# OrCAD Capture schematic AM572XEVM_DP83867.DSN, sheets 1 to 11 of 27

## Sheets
1 P01_TITLE PAGE: rev: A4; note: am572x_gp_evm_REV_A4.dsn
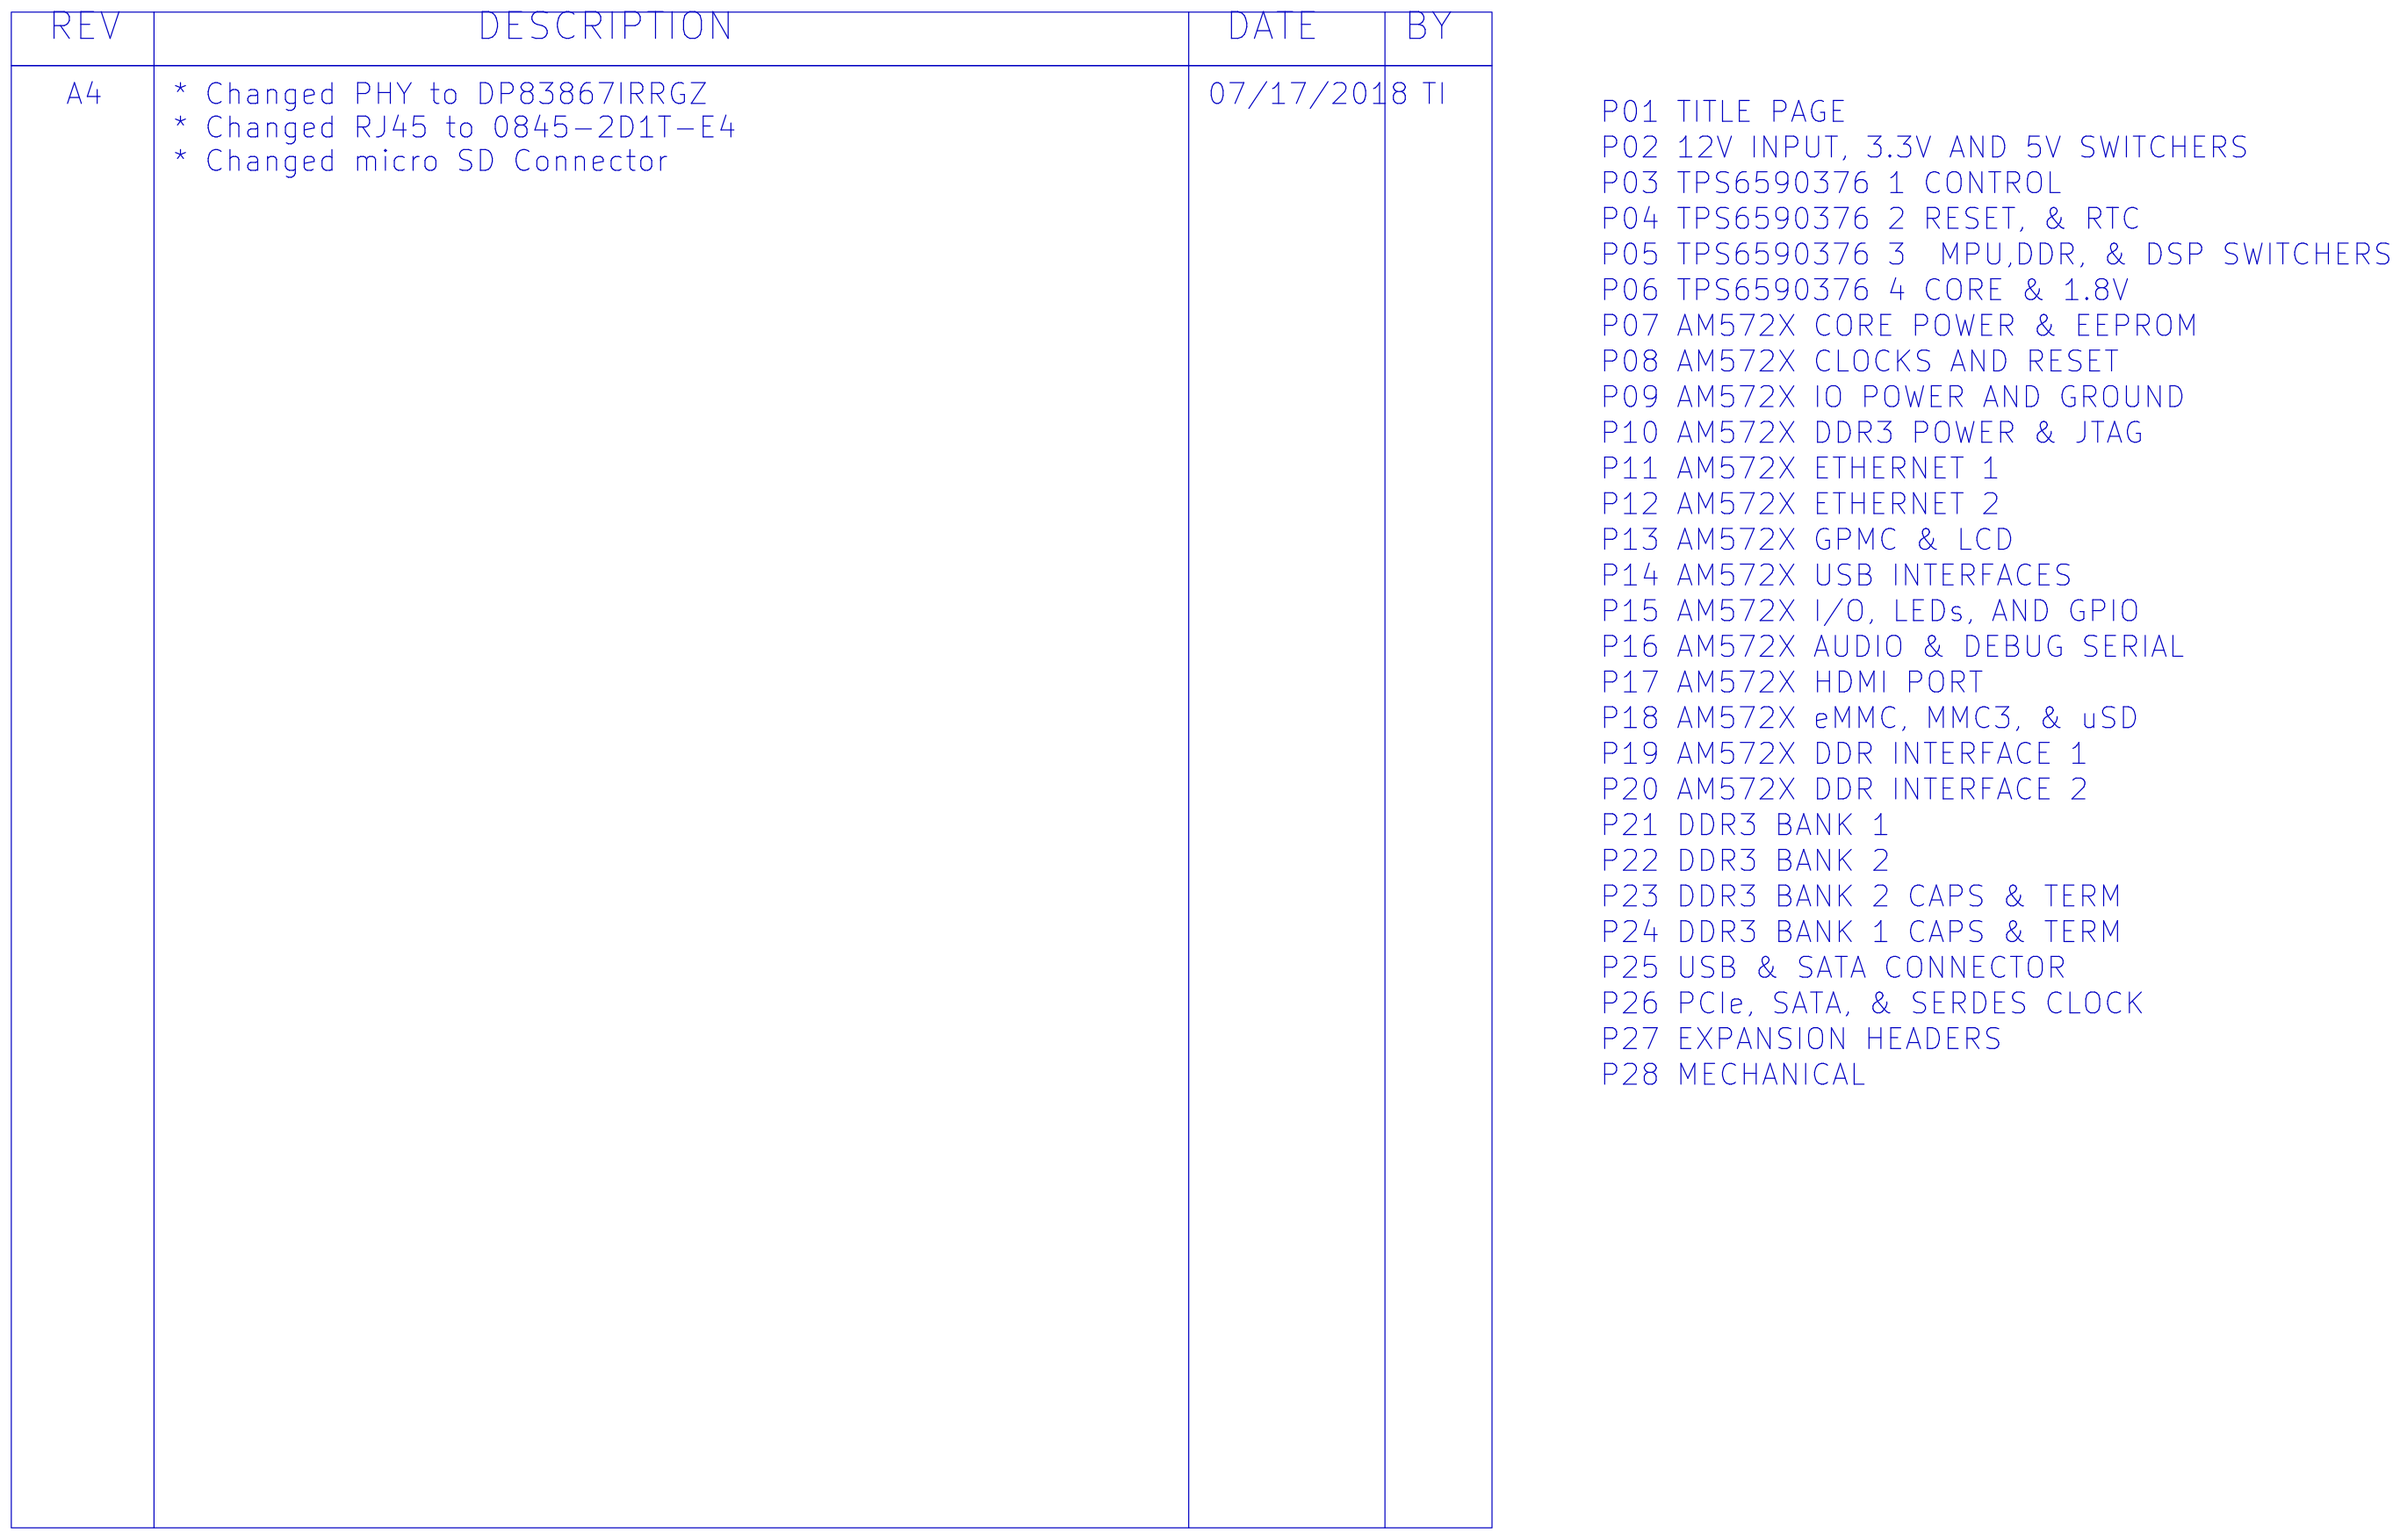
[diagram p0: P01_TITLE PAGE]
2 P02_12V IN, 3.3V & 5V SWITCHERS: size B
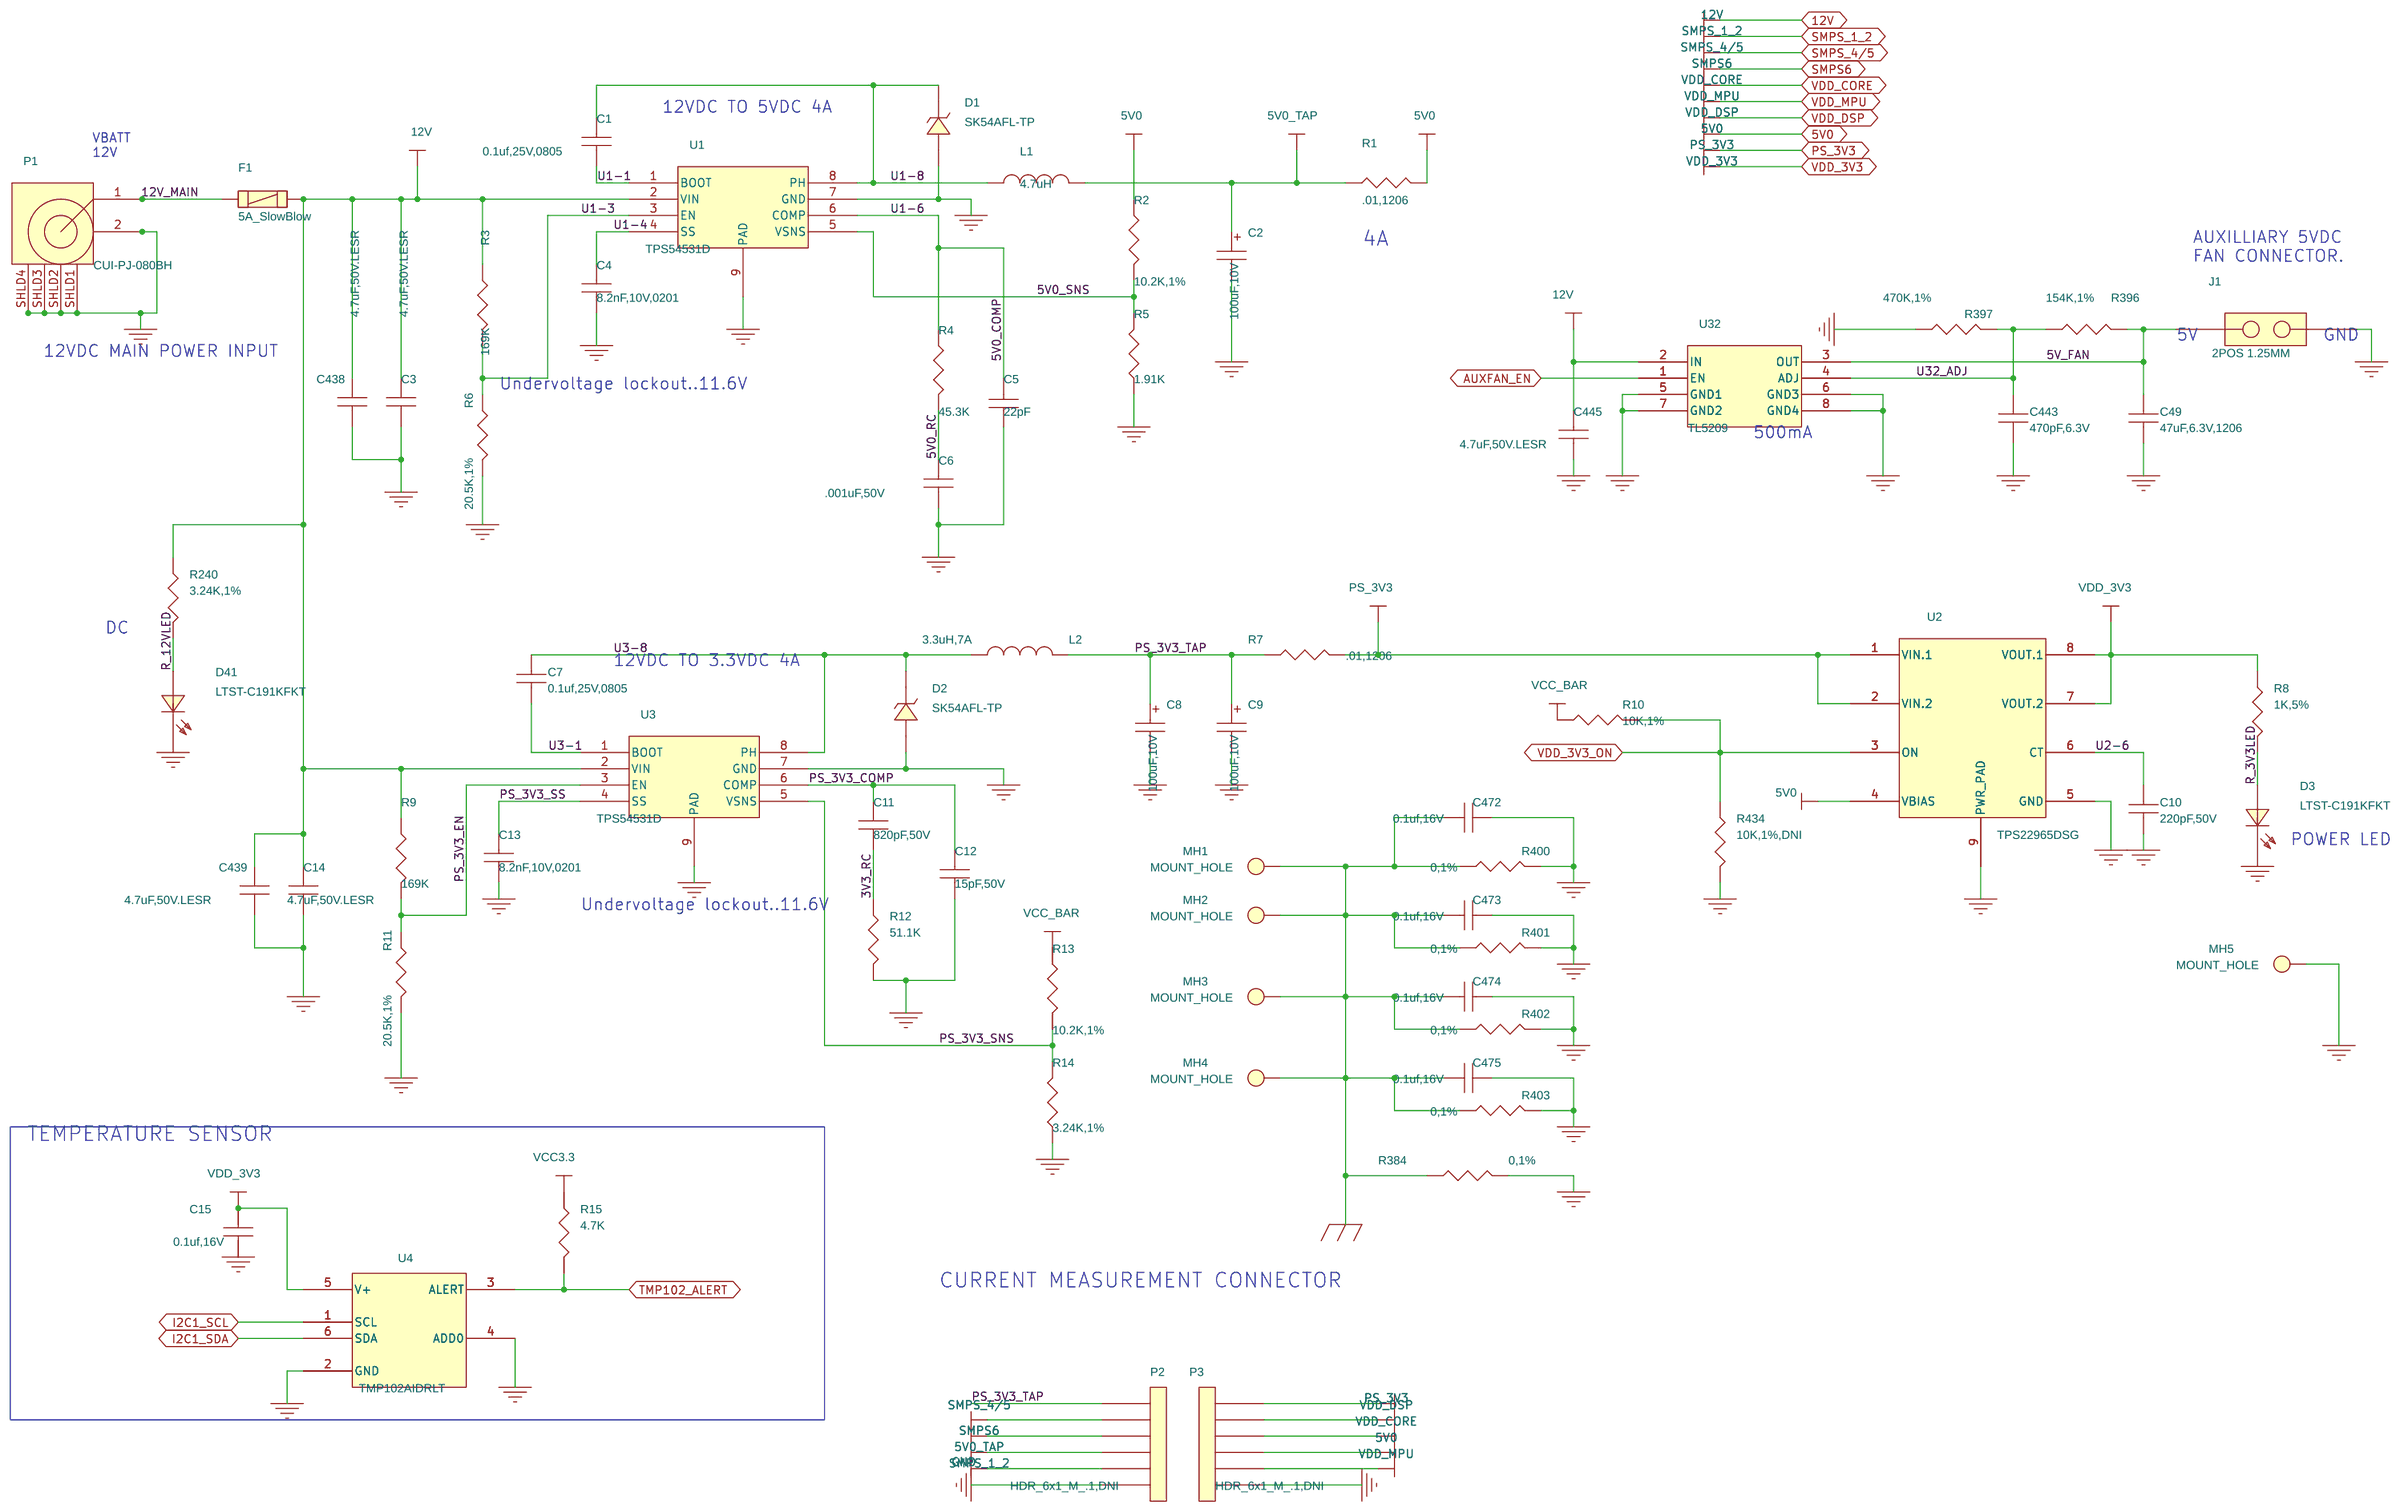
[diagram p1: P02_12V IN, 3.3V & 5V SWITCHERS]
3 P03_TPS6590376 CONTROL: size B
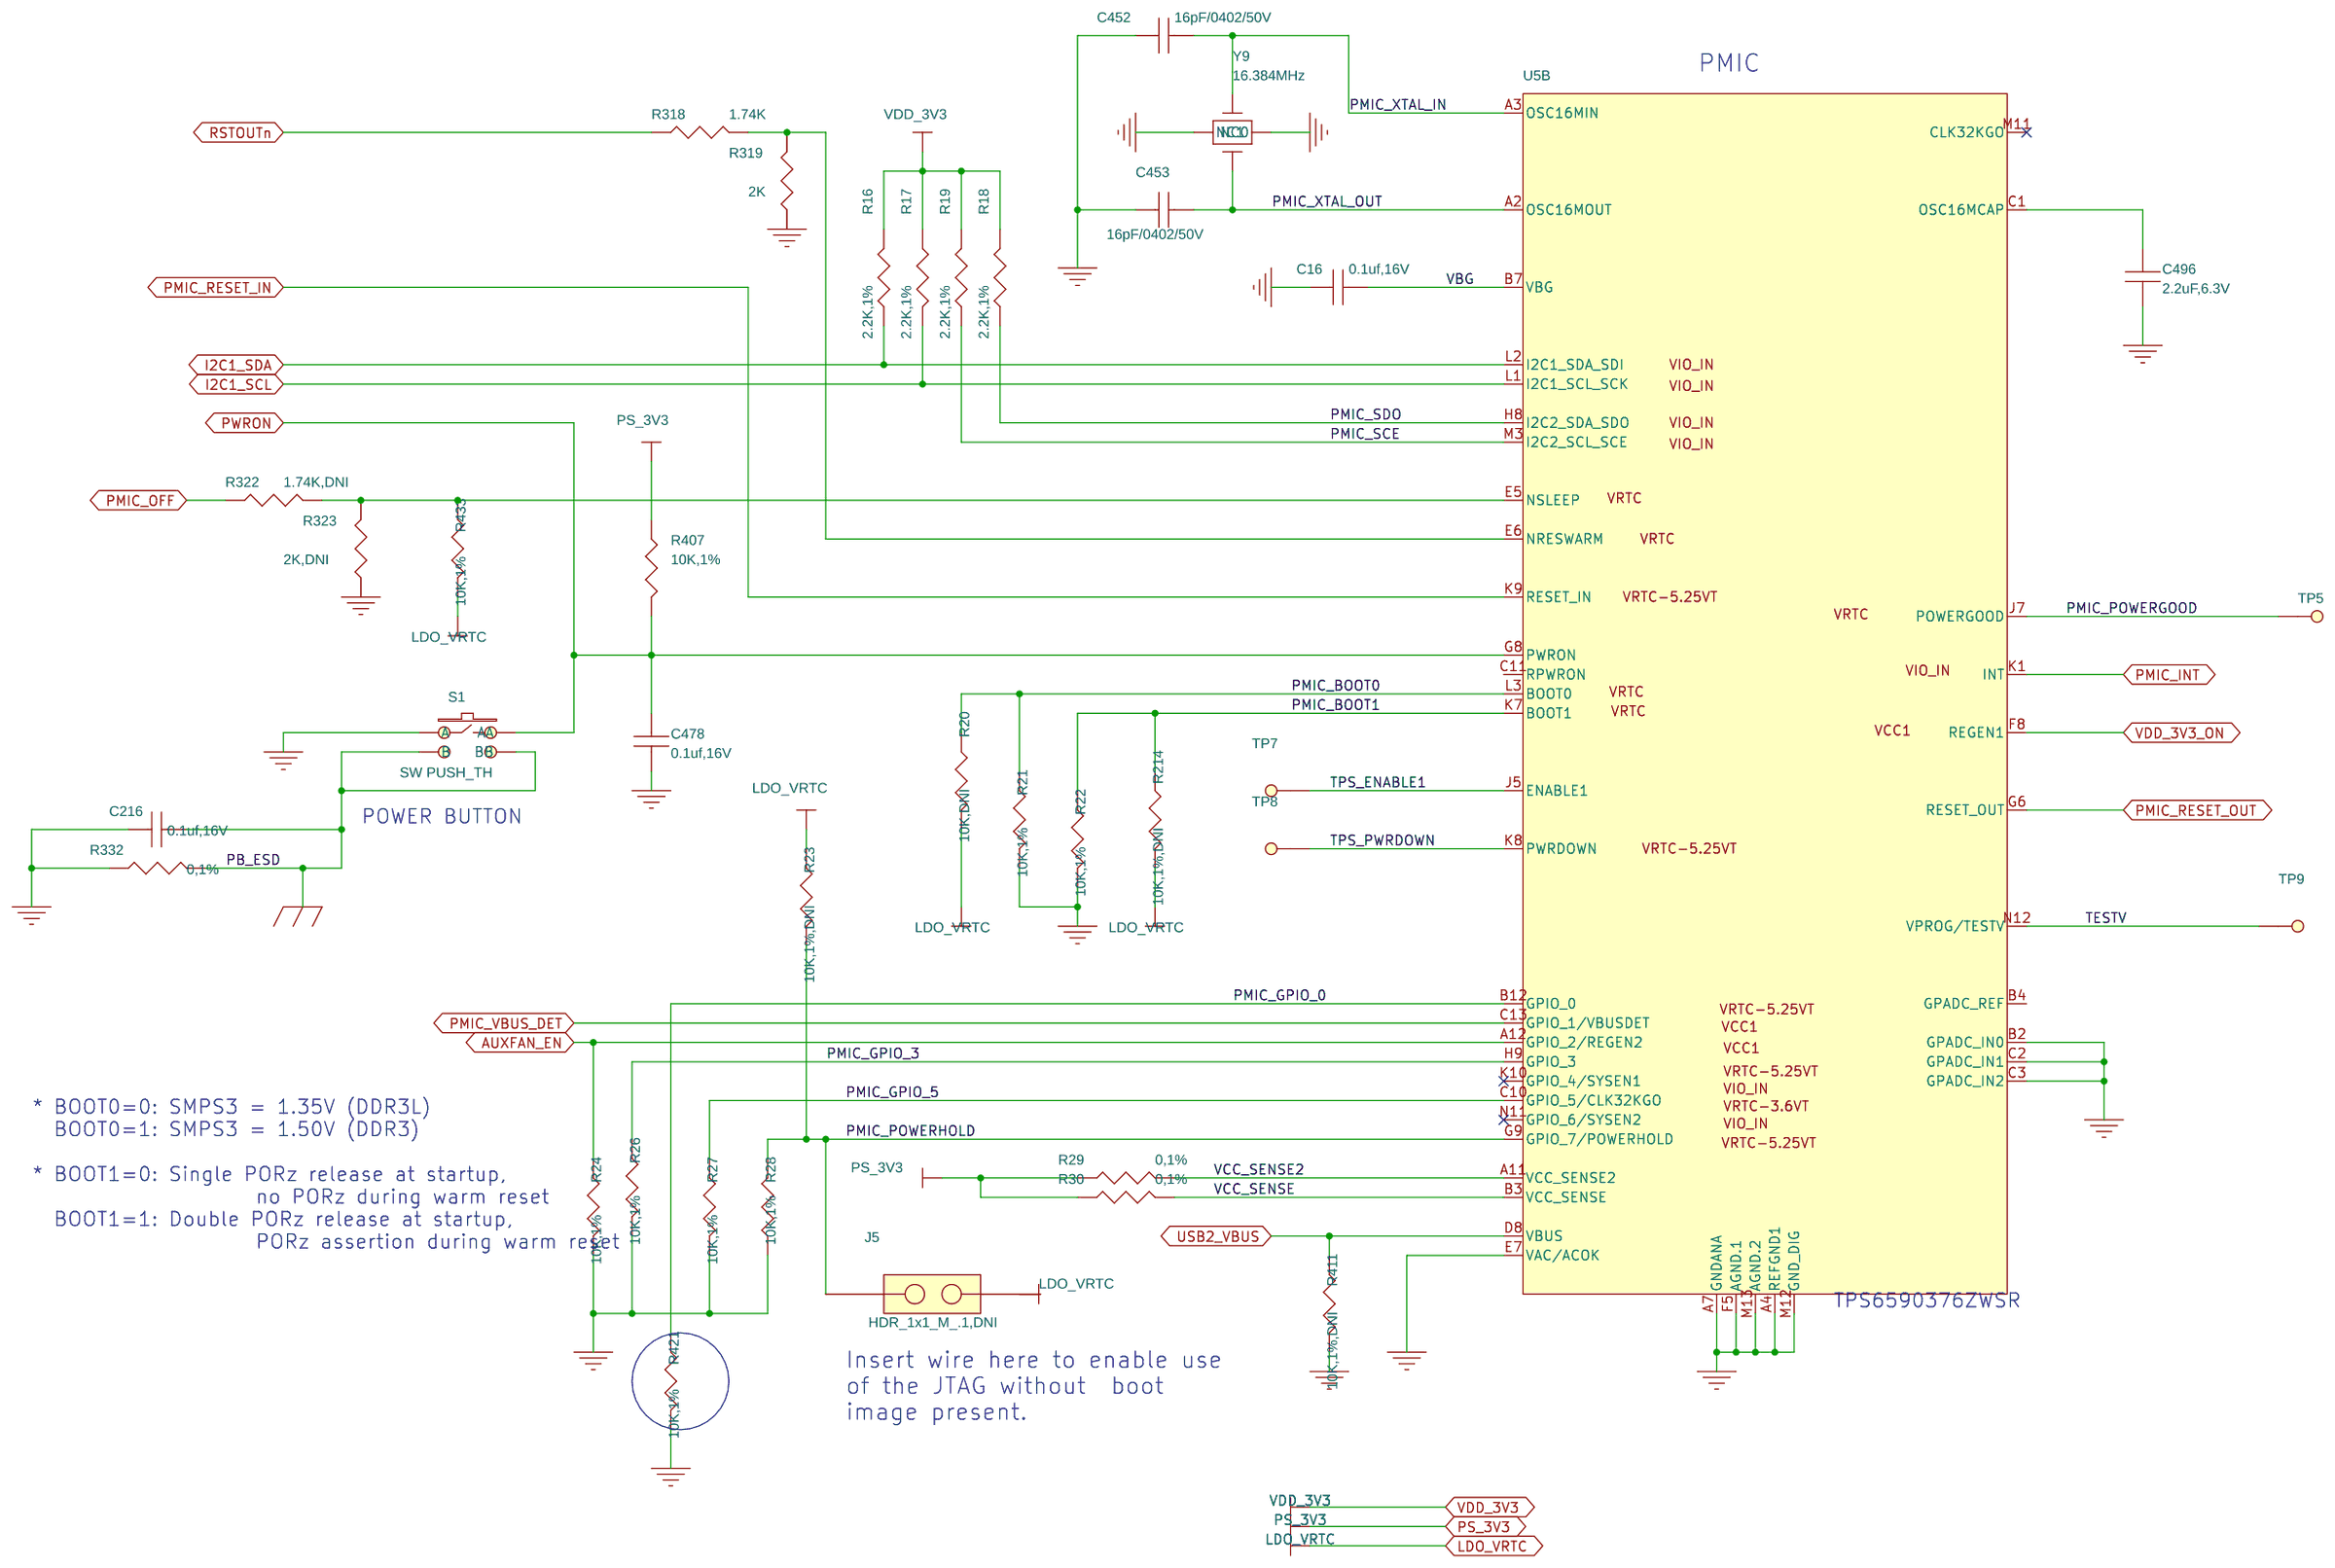
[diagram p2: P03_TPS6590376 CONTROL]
4 P04_TPS6590376 2, LDO & RTC: size B
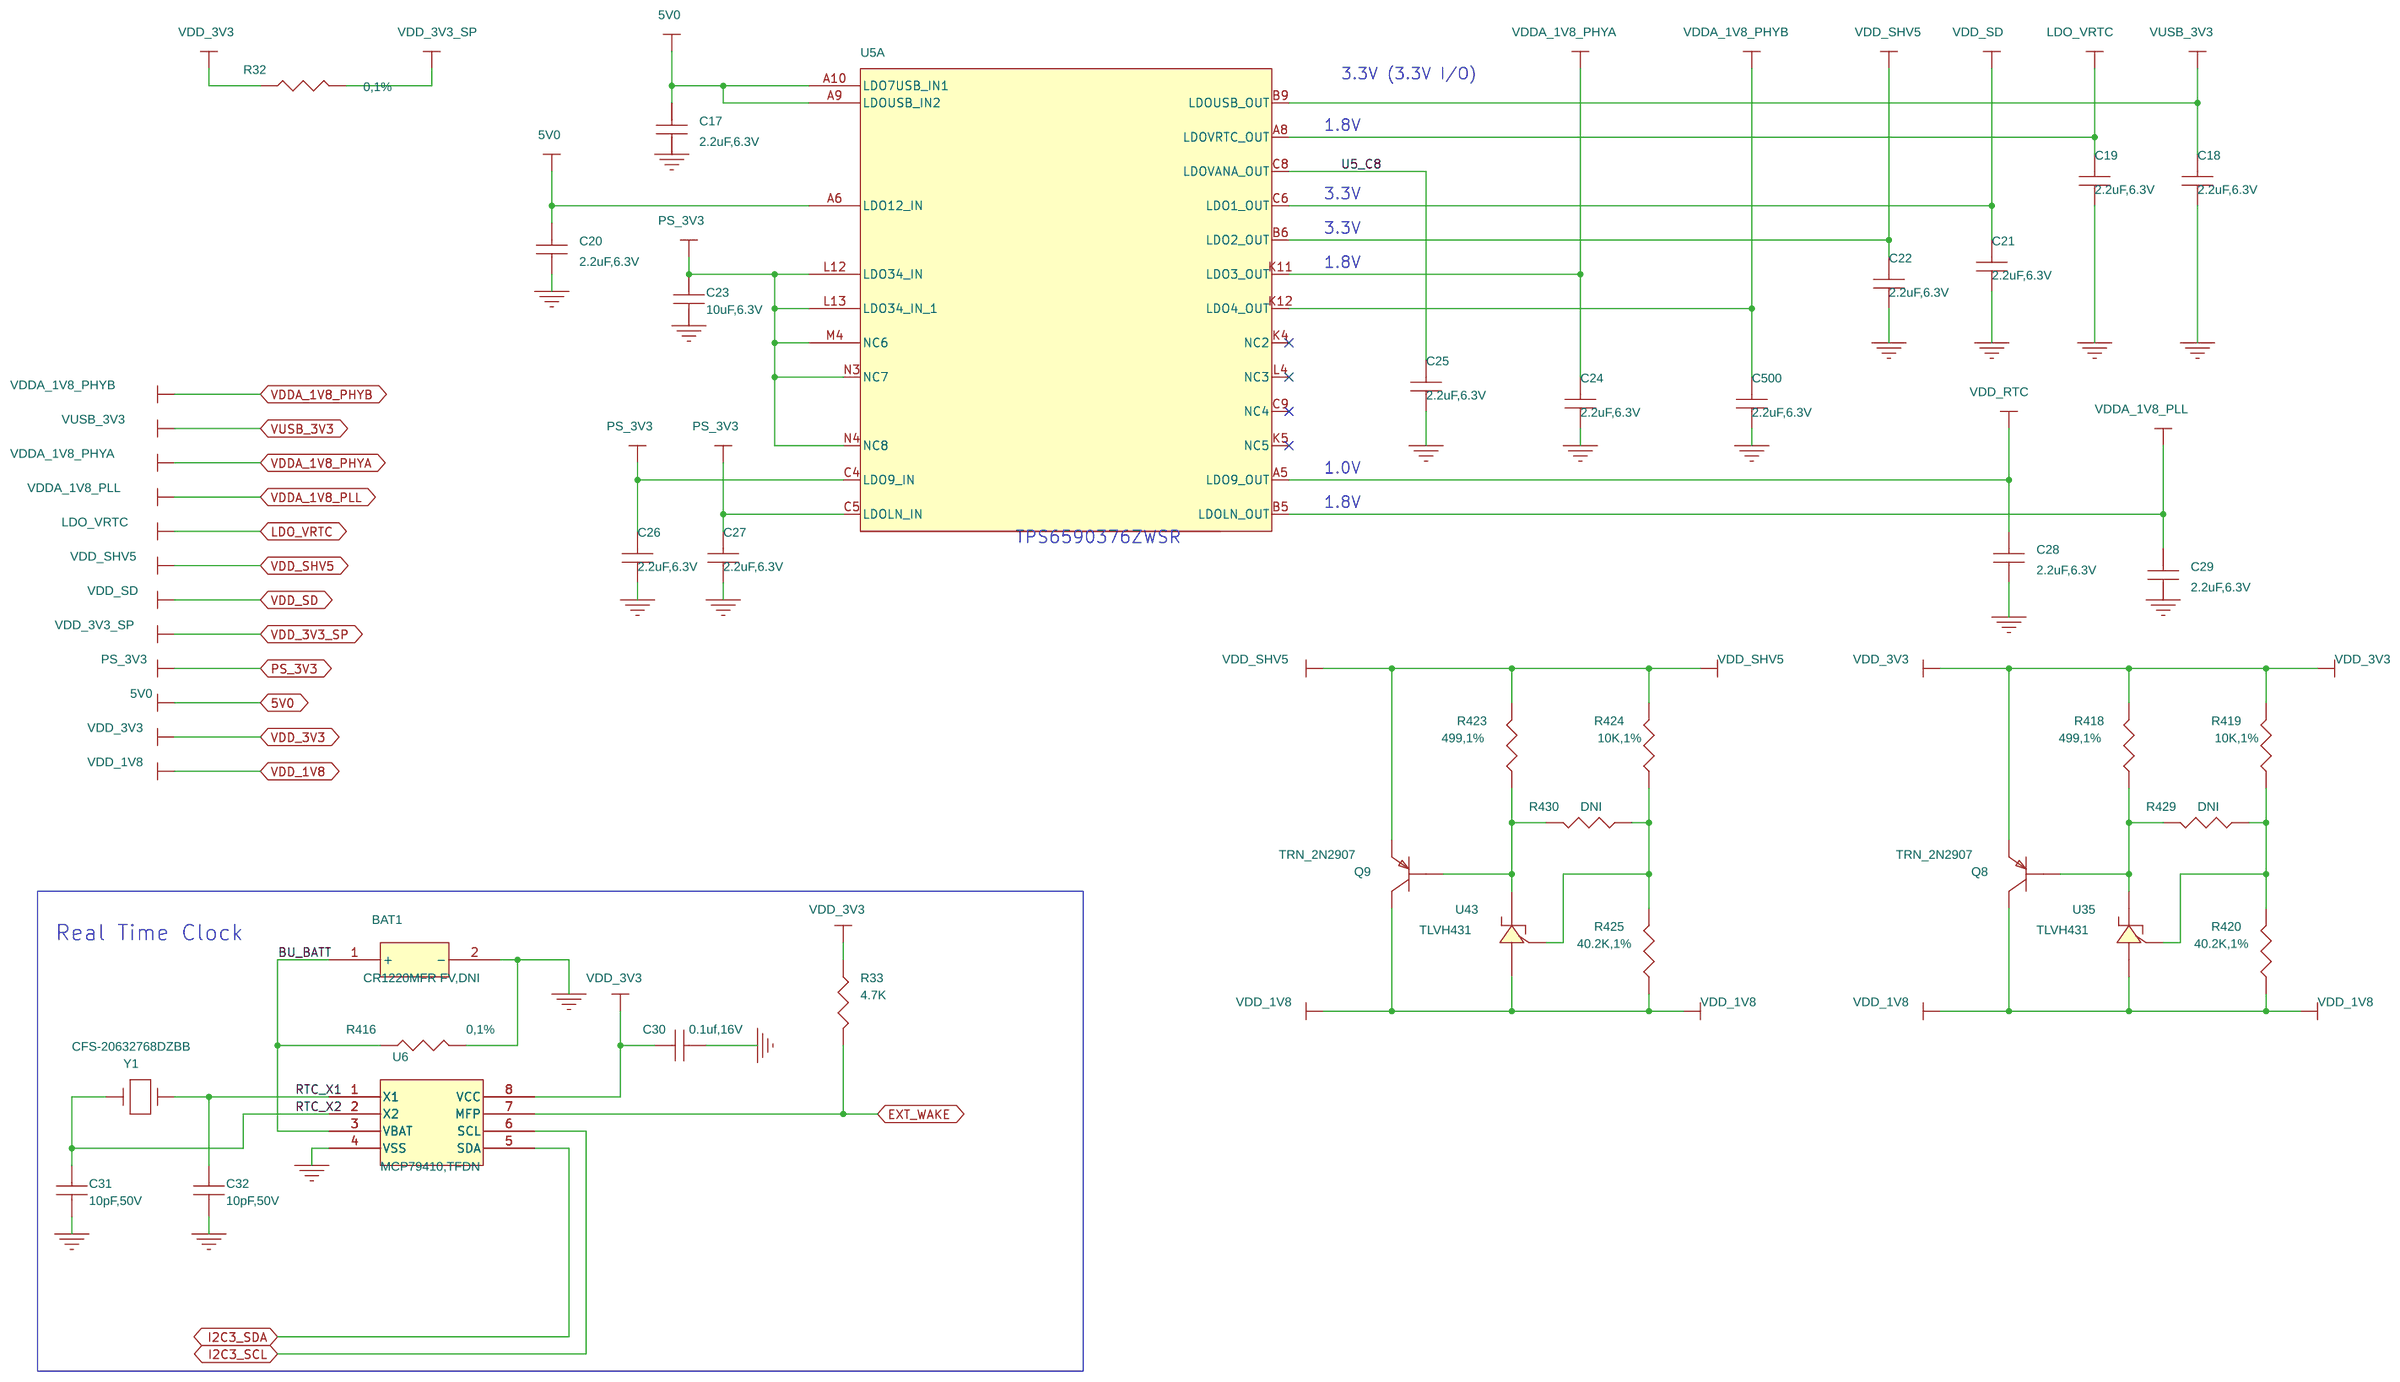
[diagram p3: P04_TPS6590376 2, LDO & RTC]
5 P05_TPS6590376 3 MPU,DSP SWITCH: size B
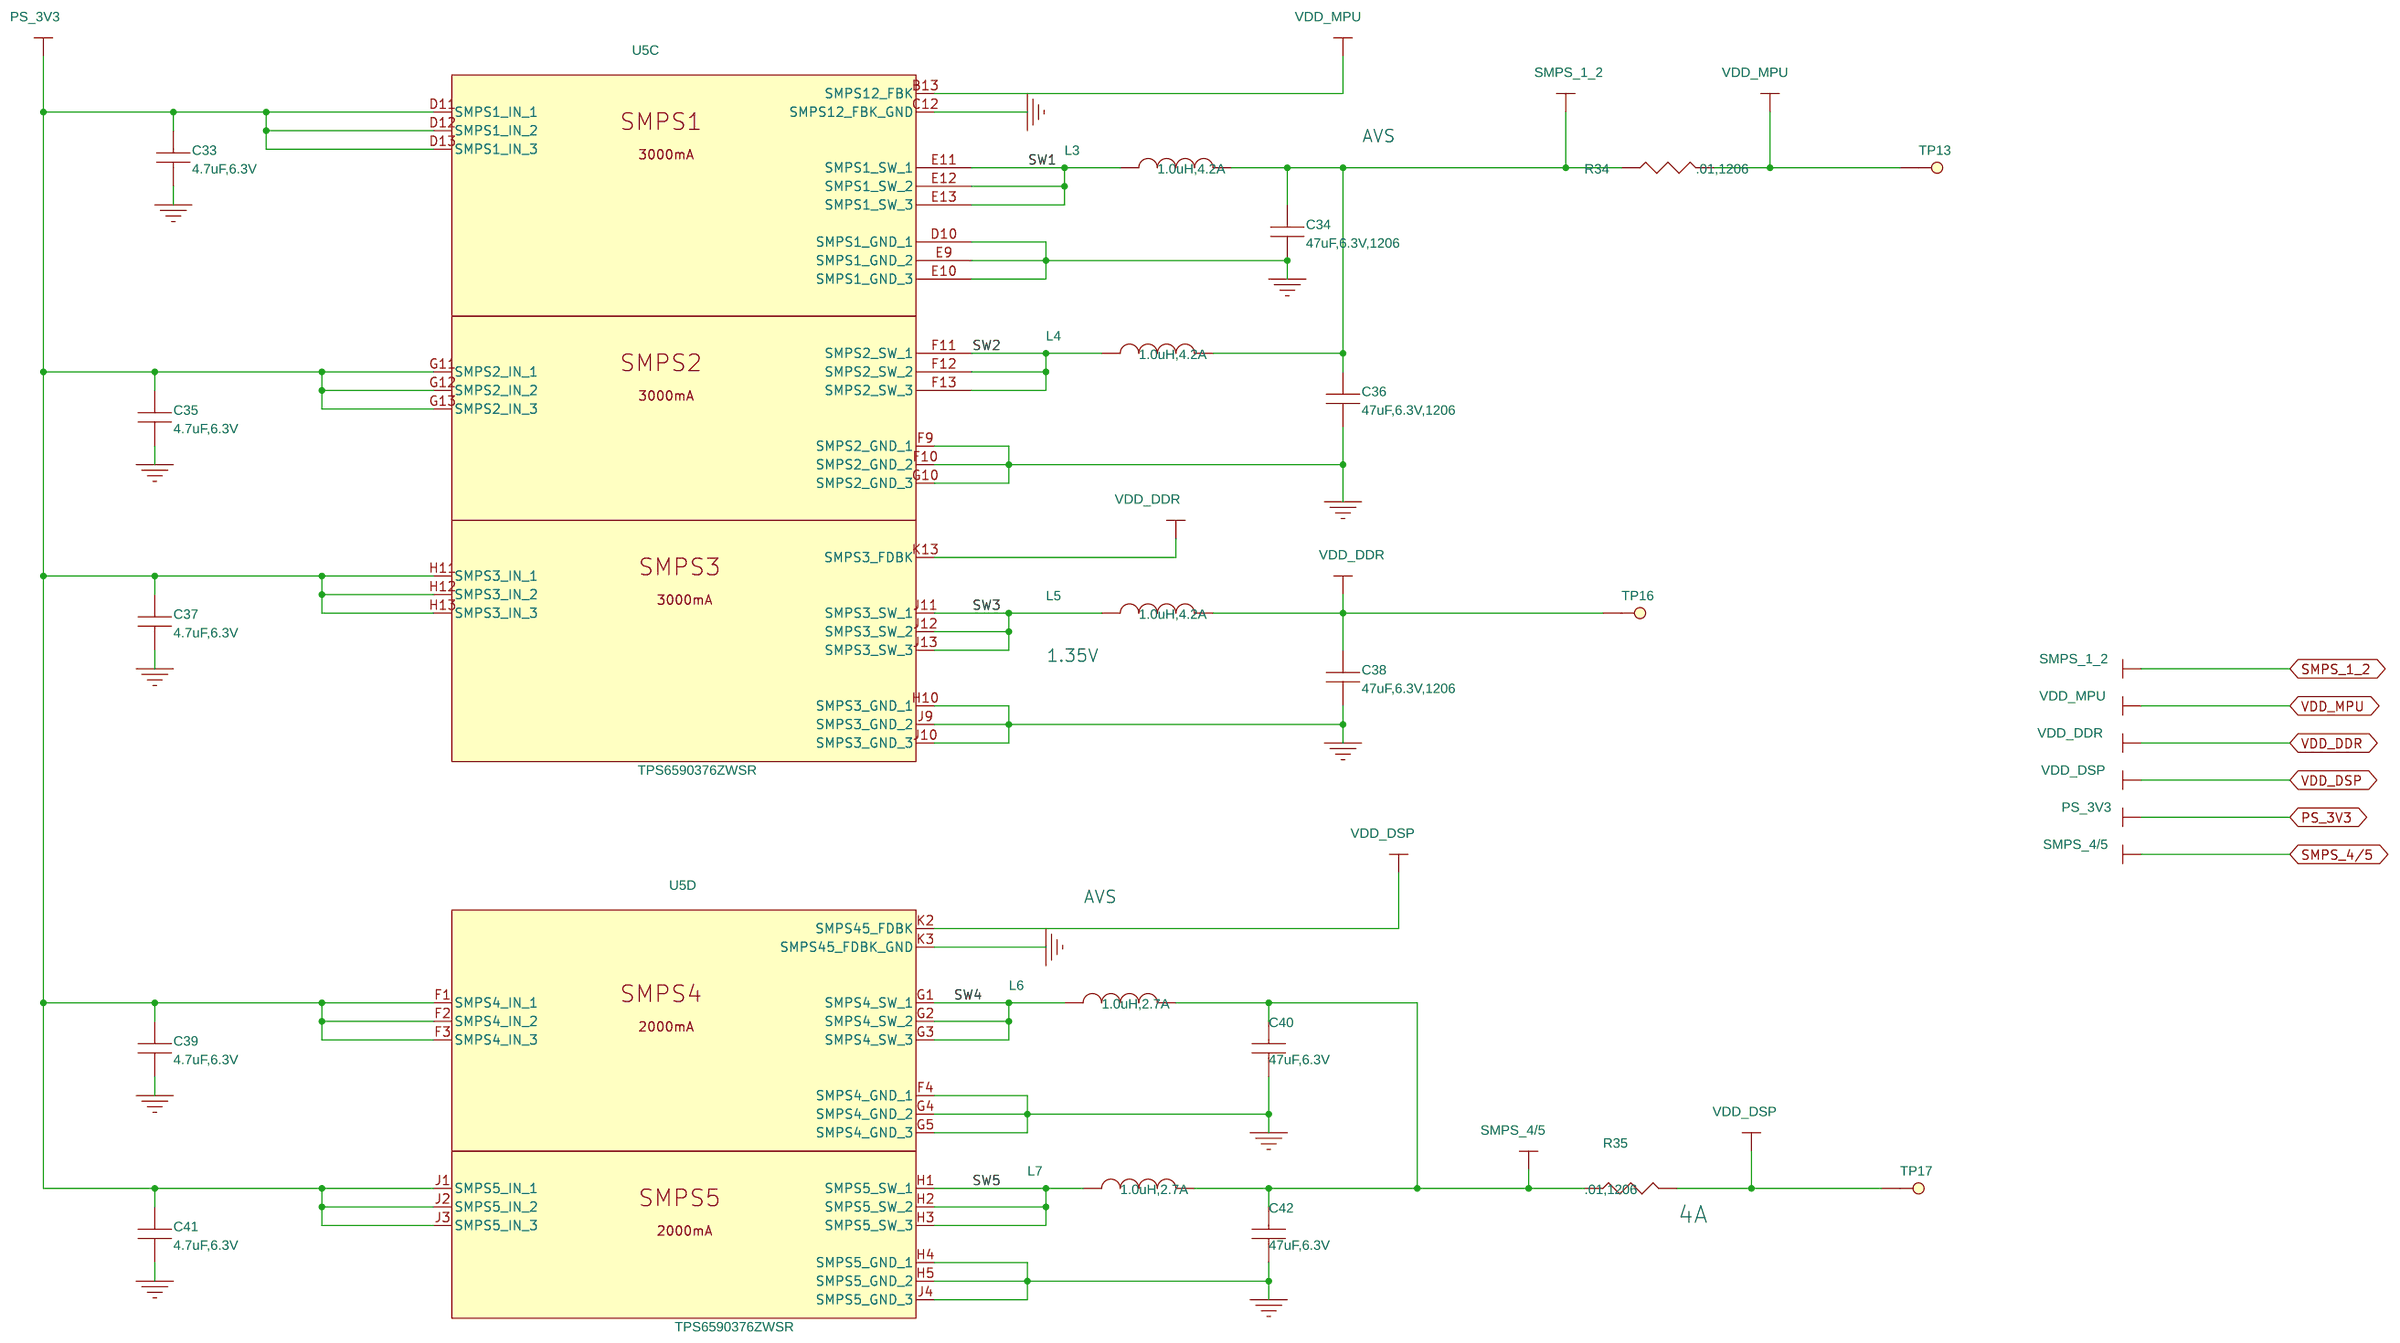
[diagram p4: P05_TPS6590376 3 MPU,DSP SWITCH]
6 P06_TPS6590376 4 CORE & 1.8V: size B
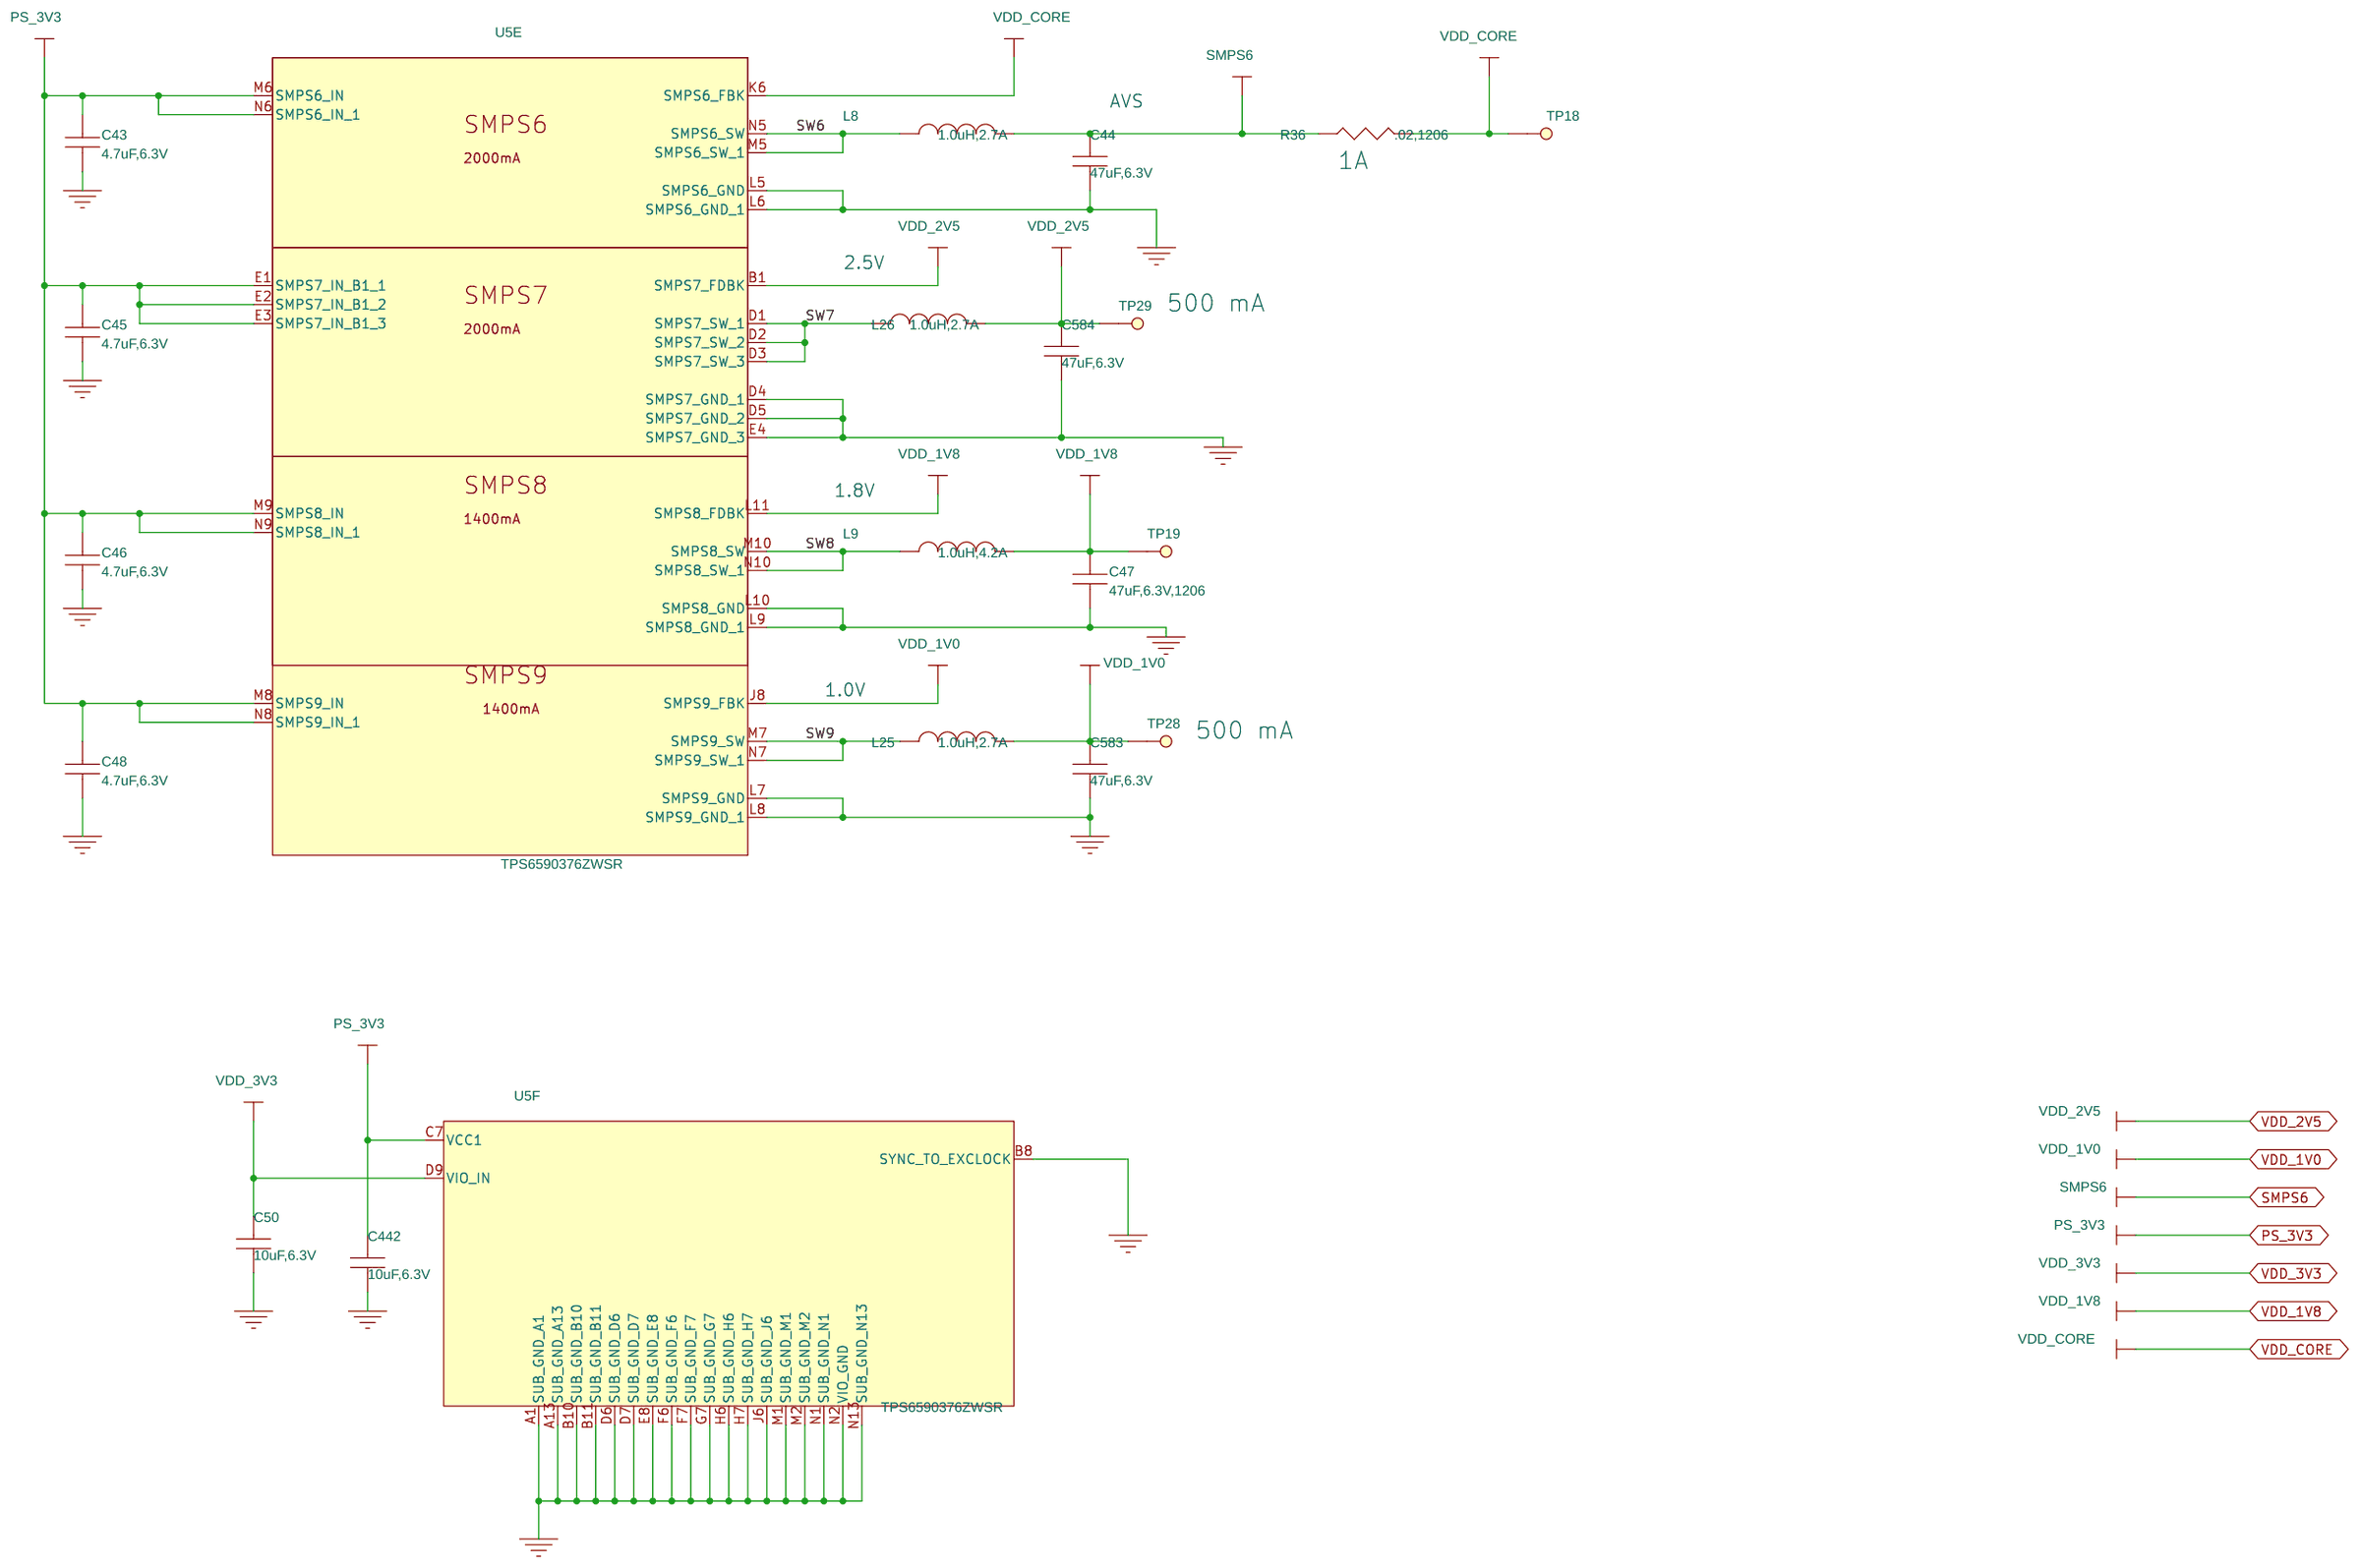
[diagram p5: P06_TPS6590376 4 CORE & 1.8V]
7 P07_AM572x CORE POWER & EEPROM: size B
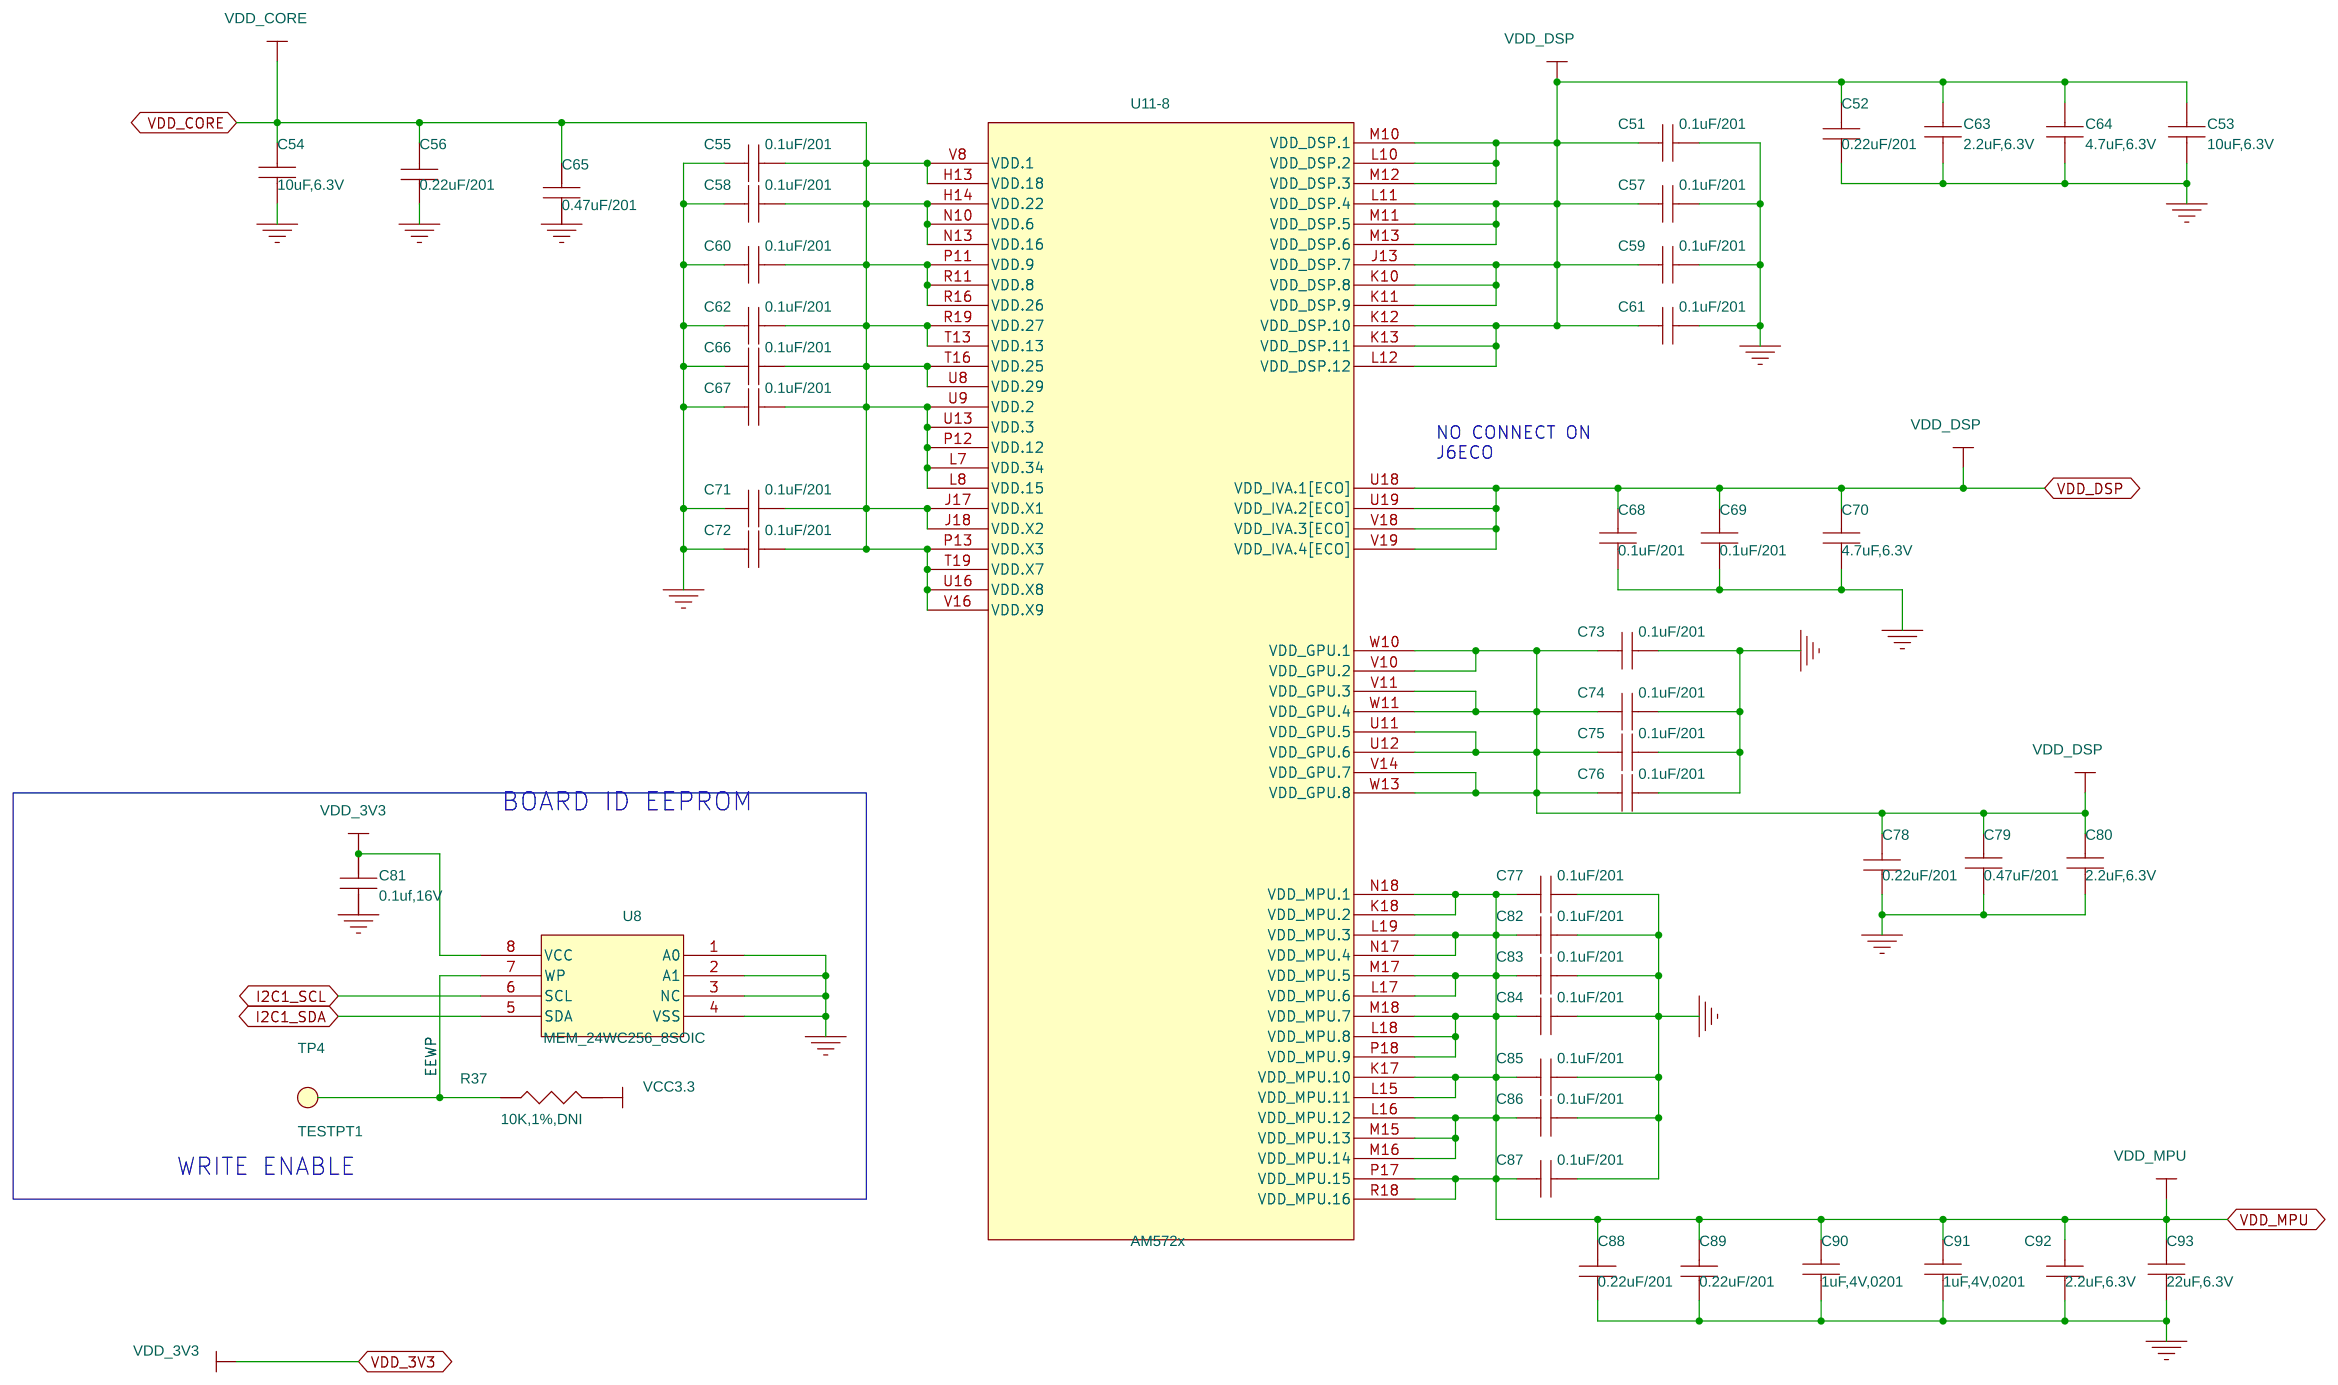
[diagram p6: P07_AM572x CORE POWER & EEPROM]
8 P08_AM572x CLOCKS & RESET: size B
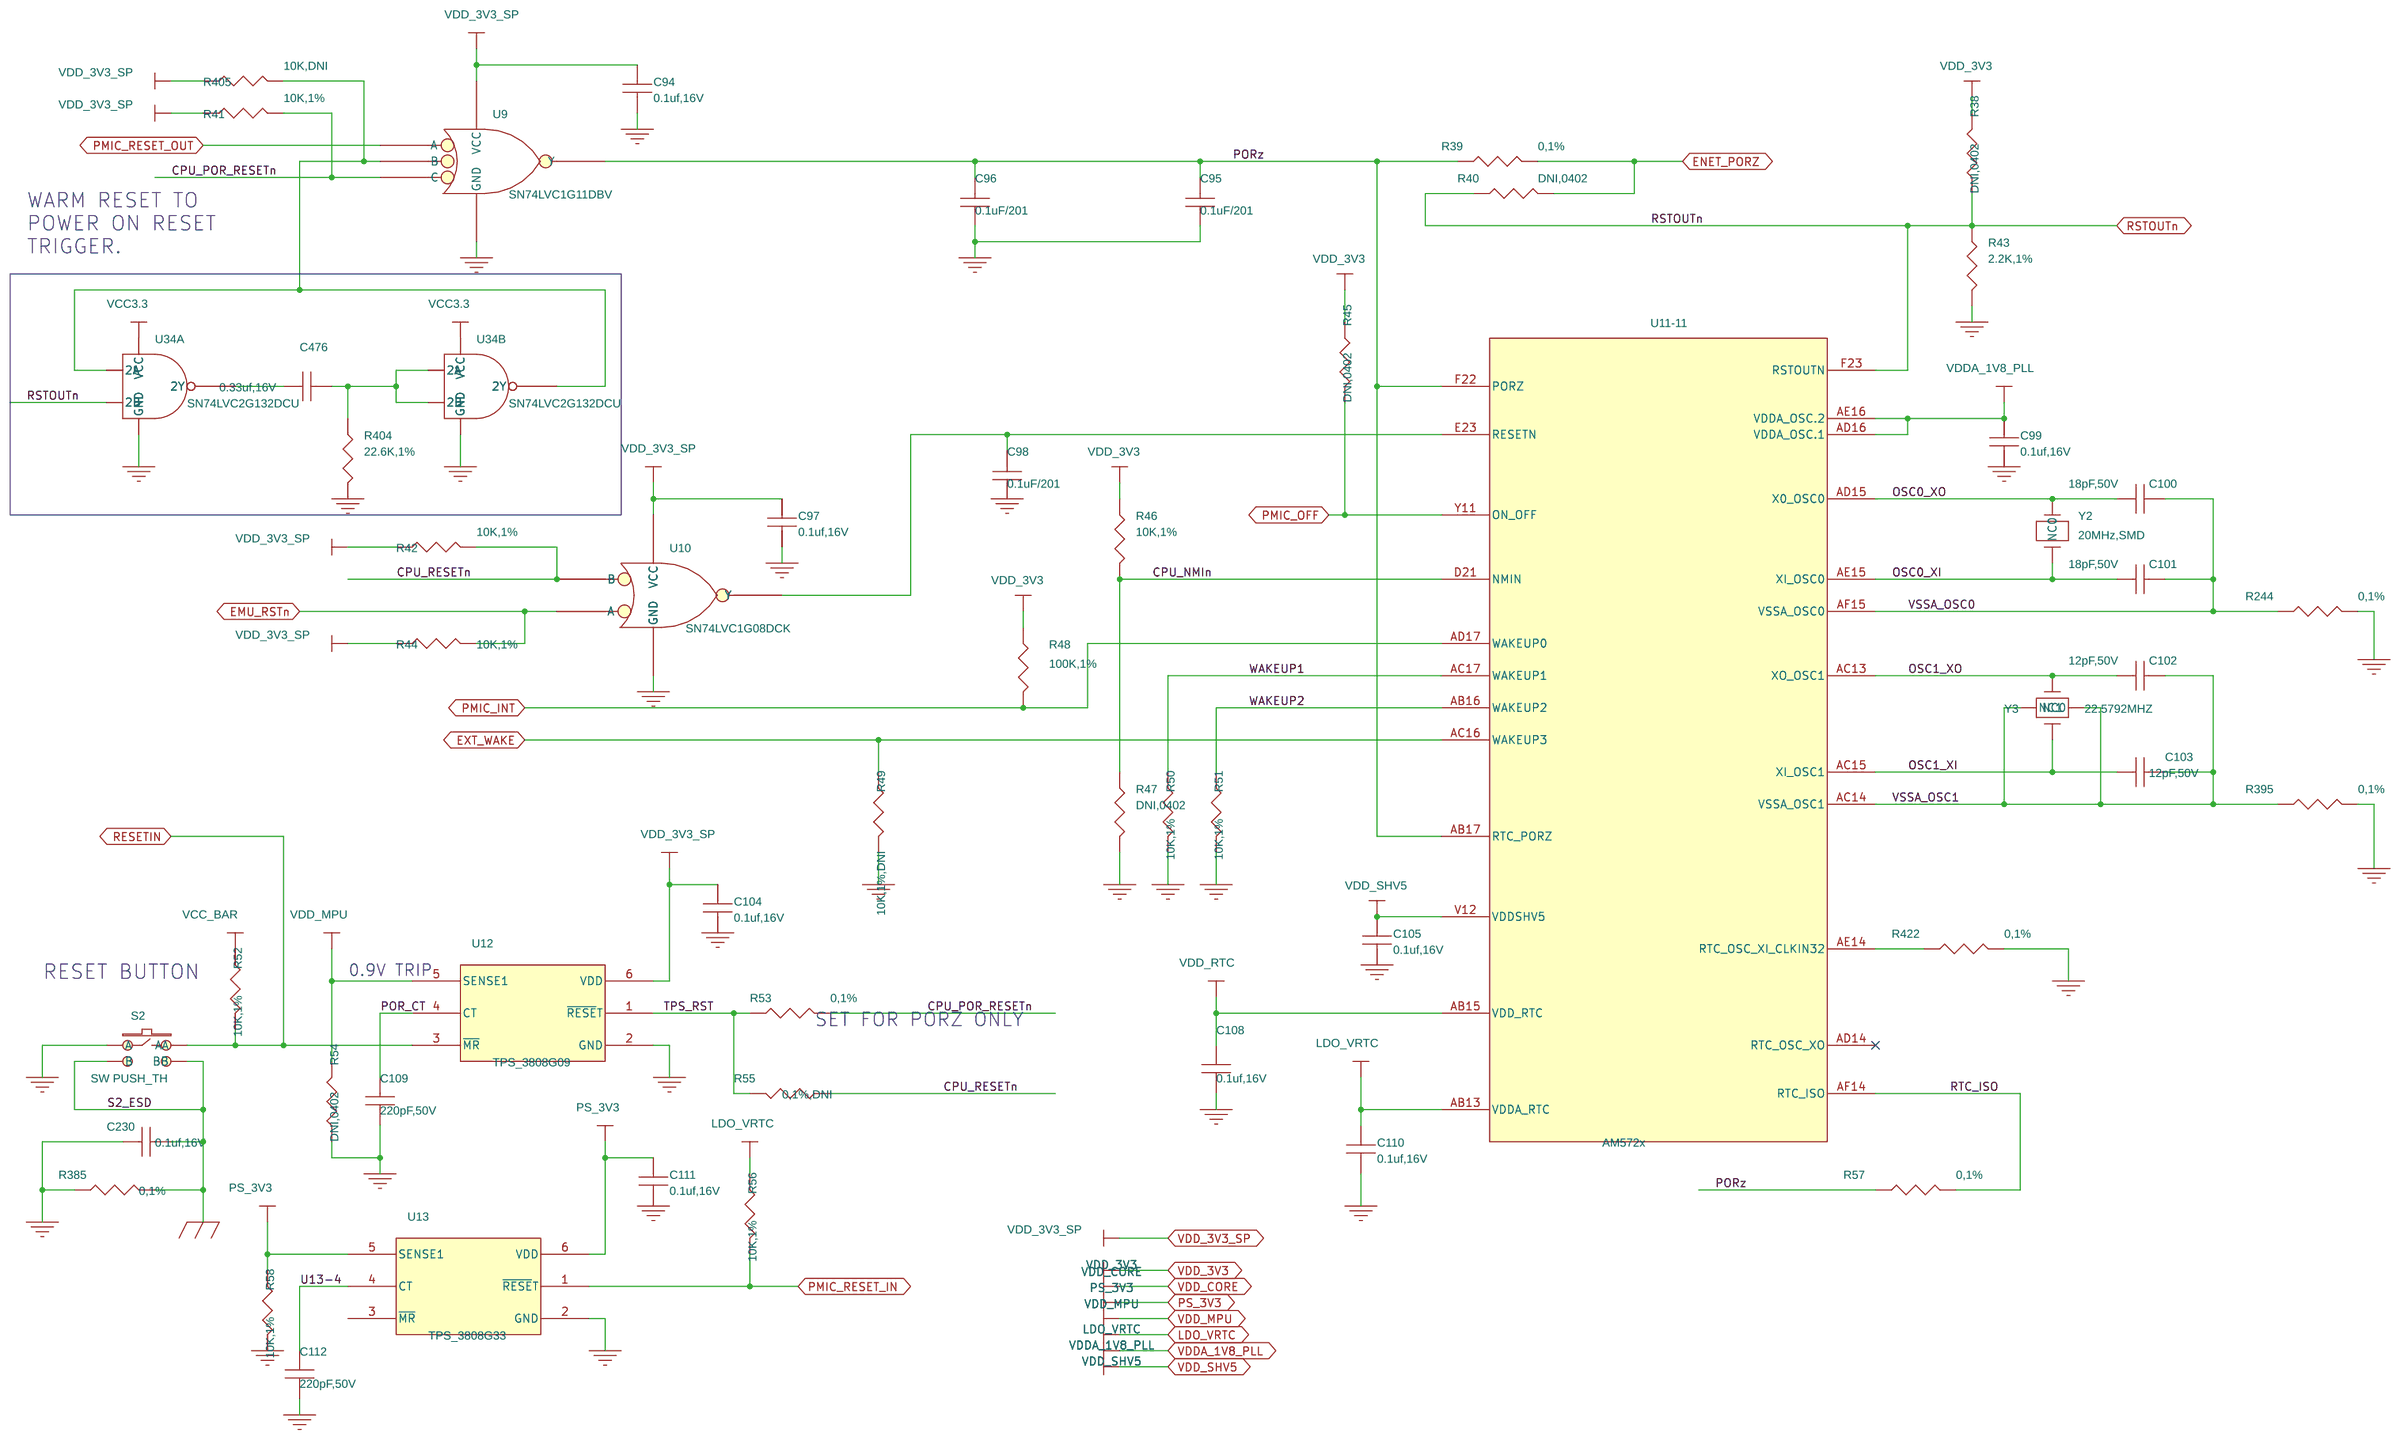
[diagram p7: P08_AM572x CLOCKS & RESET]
9 P09 AM572x IO POWER & GND: size B
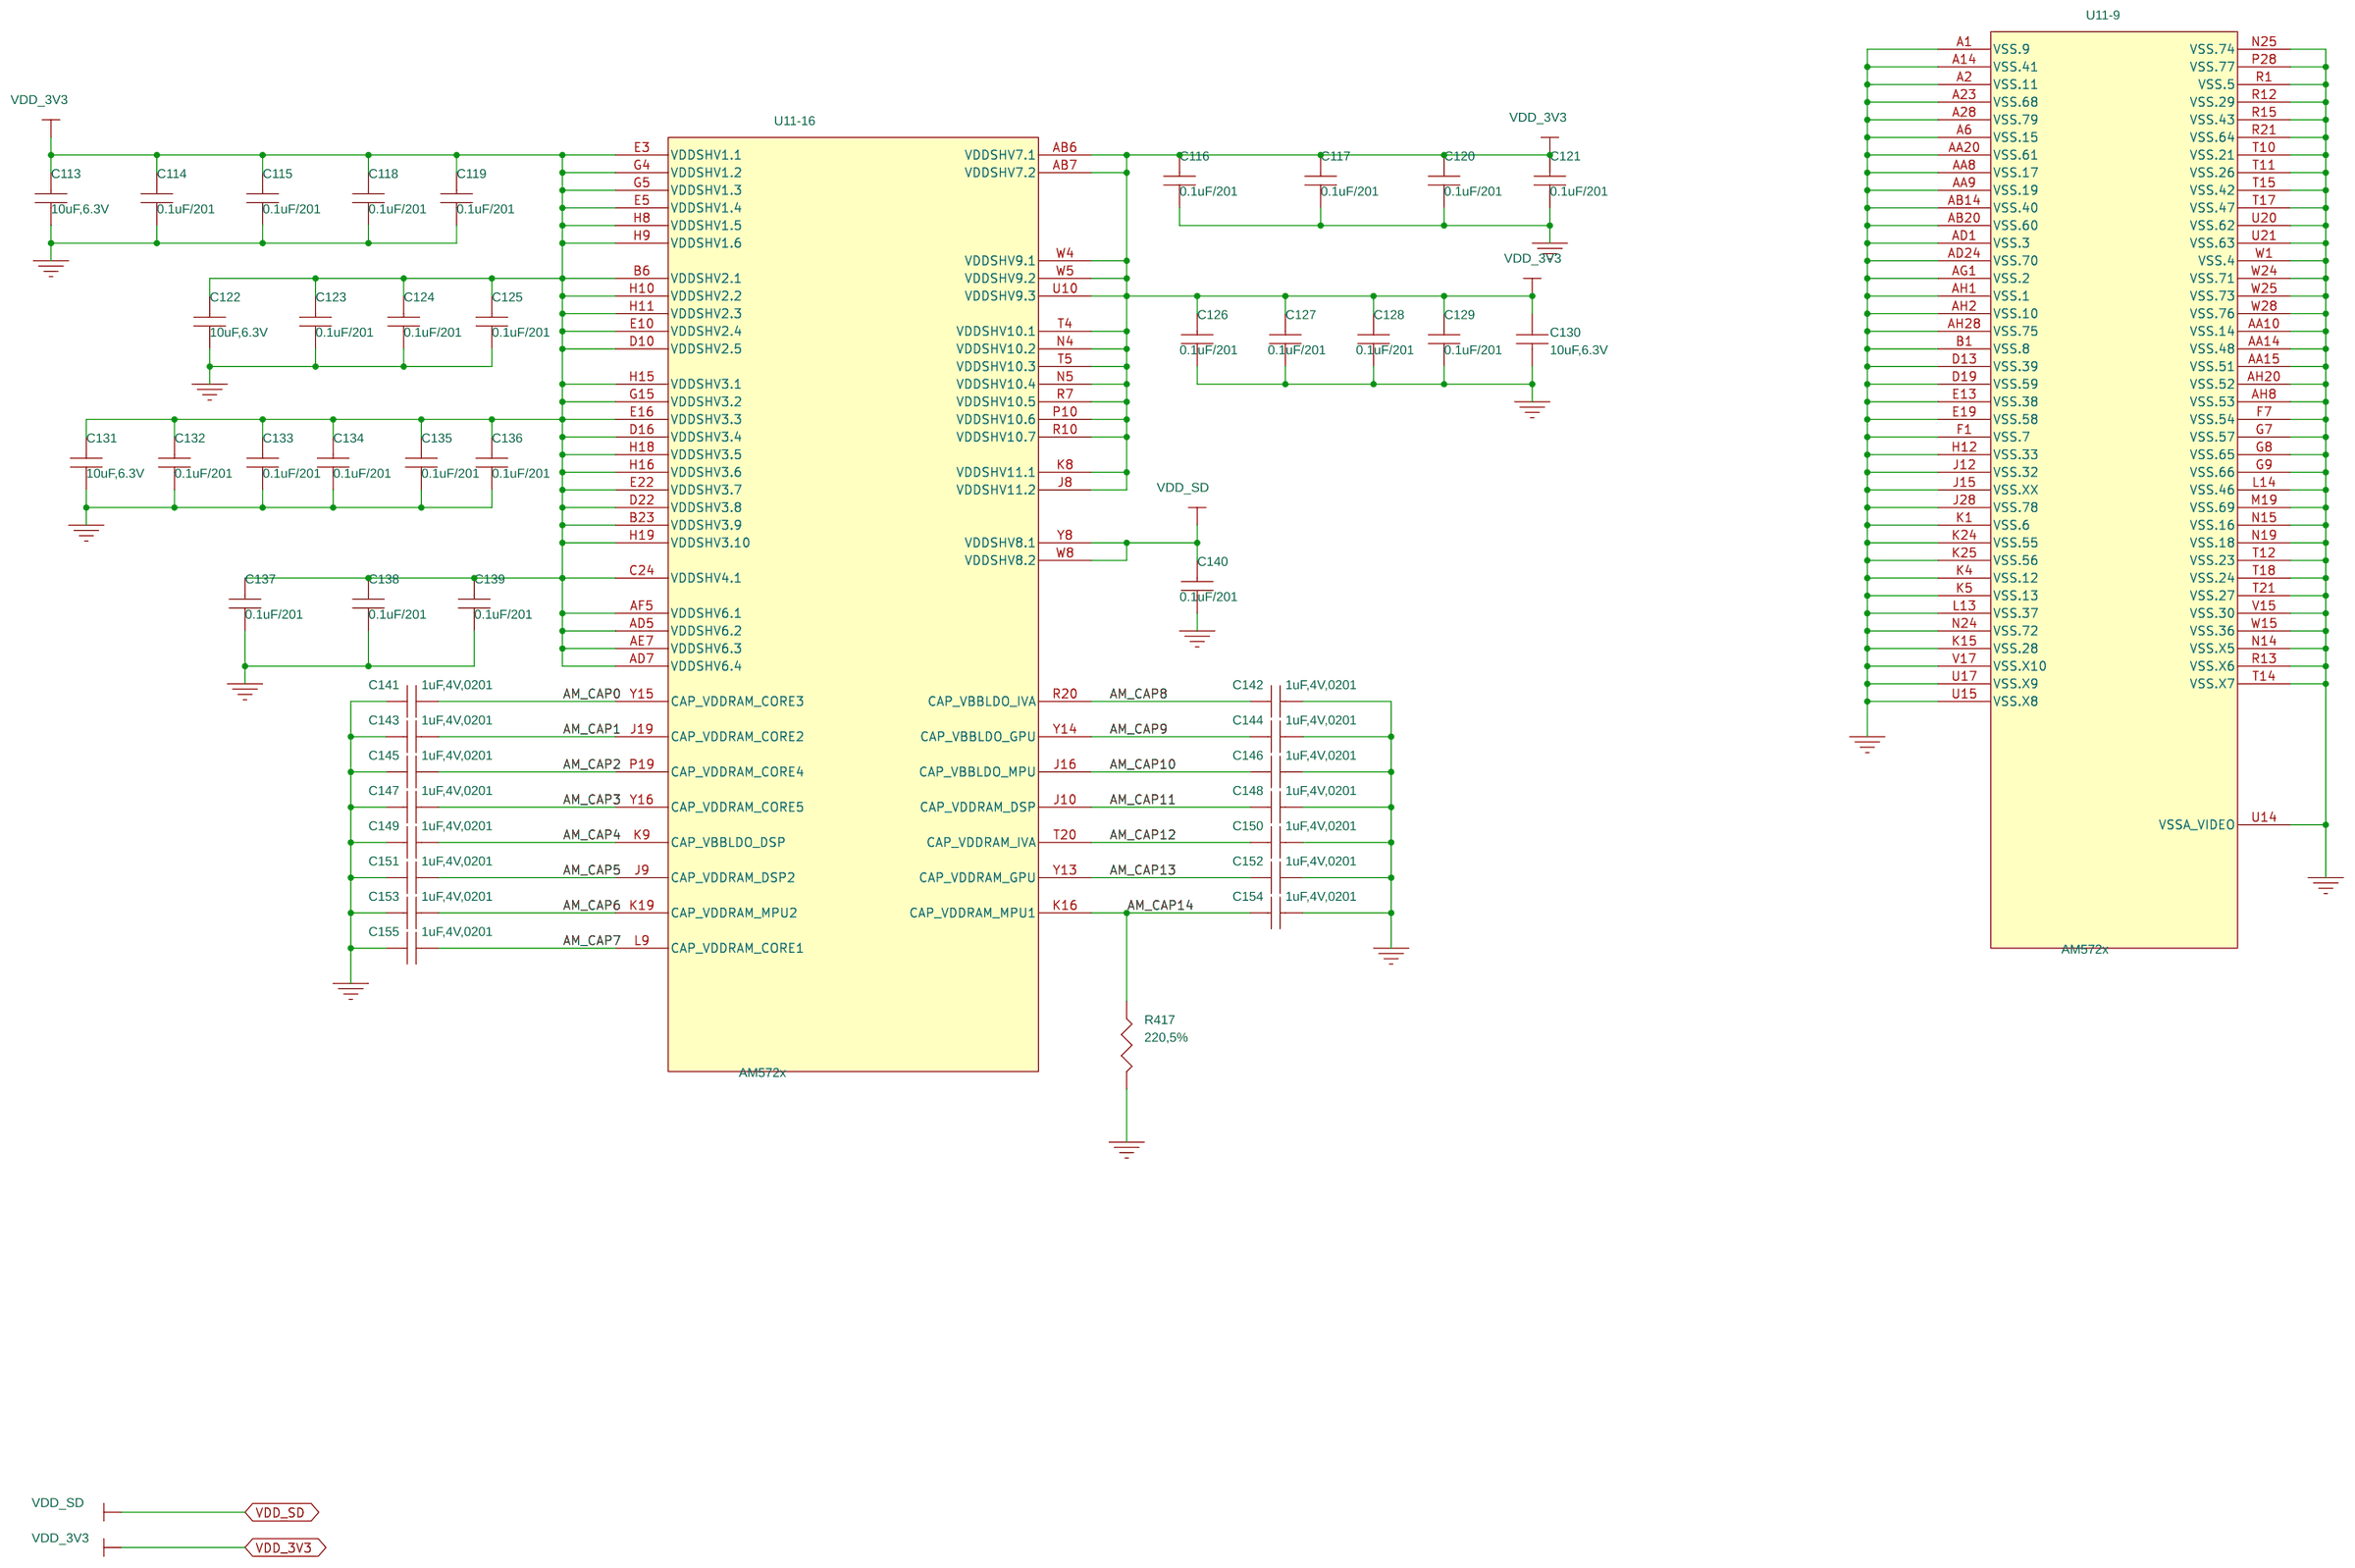
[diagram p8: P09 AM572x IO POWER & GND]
10 P10_AM572x  DDR3 POWER, & JTAG: size B
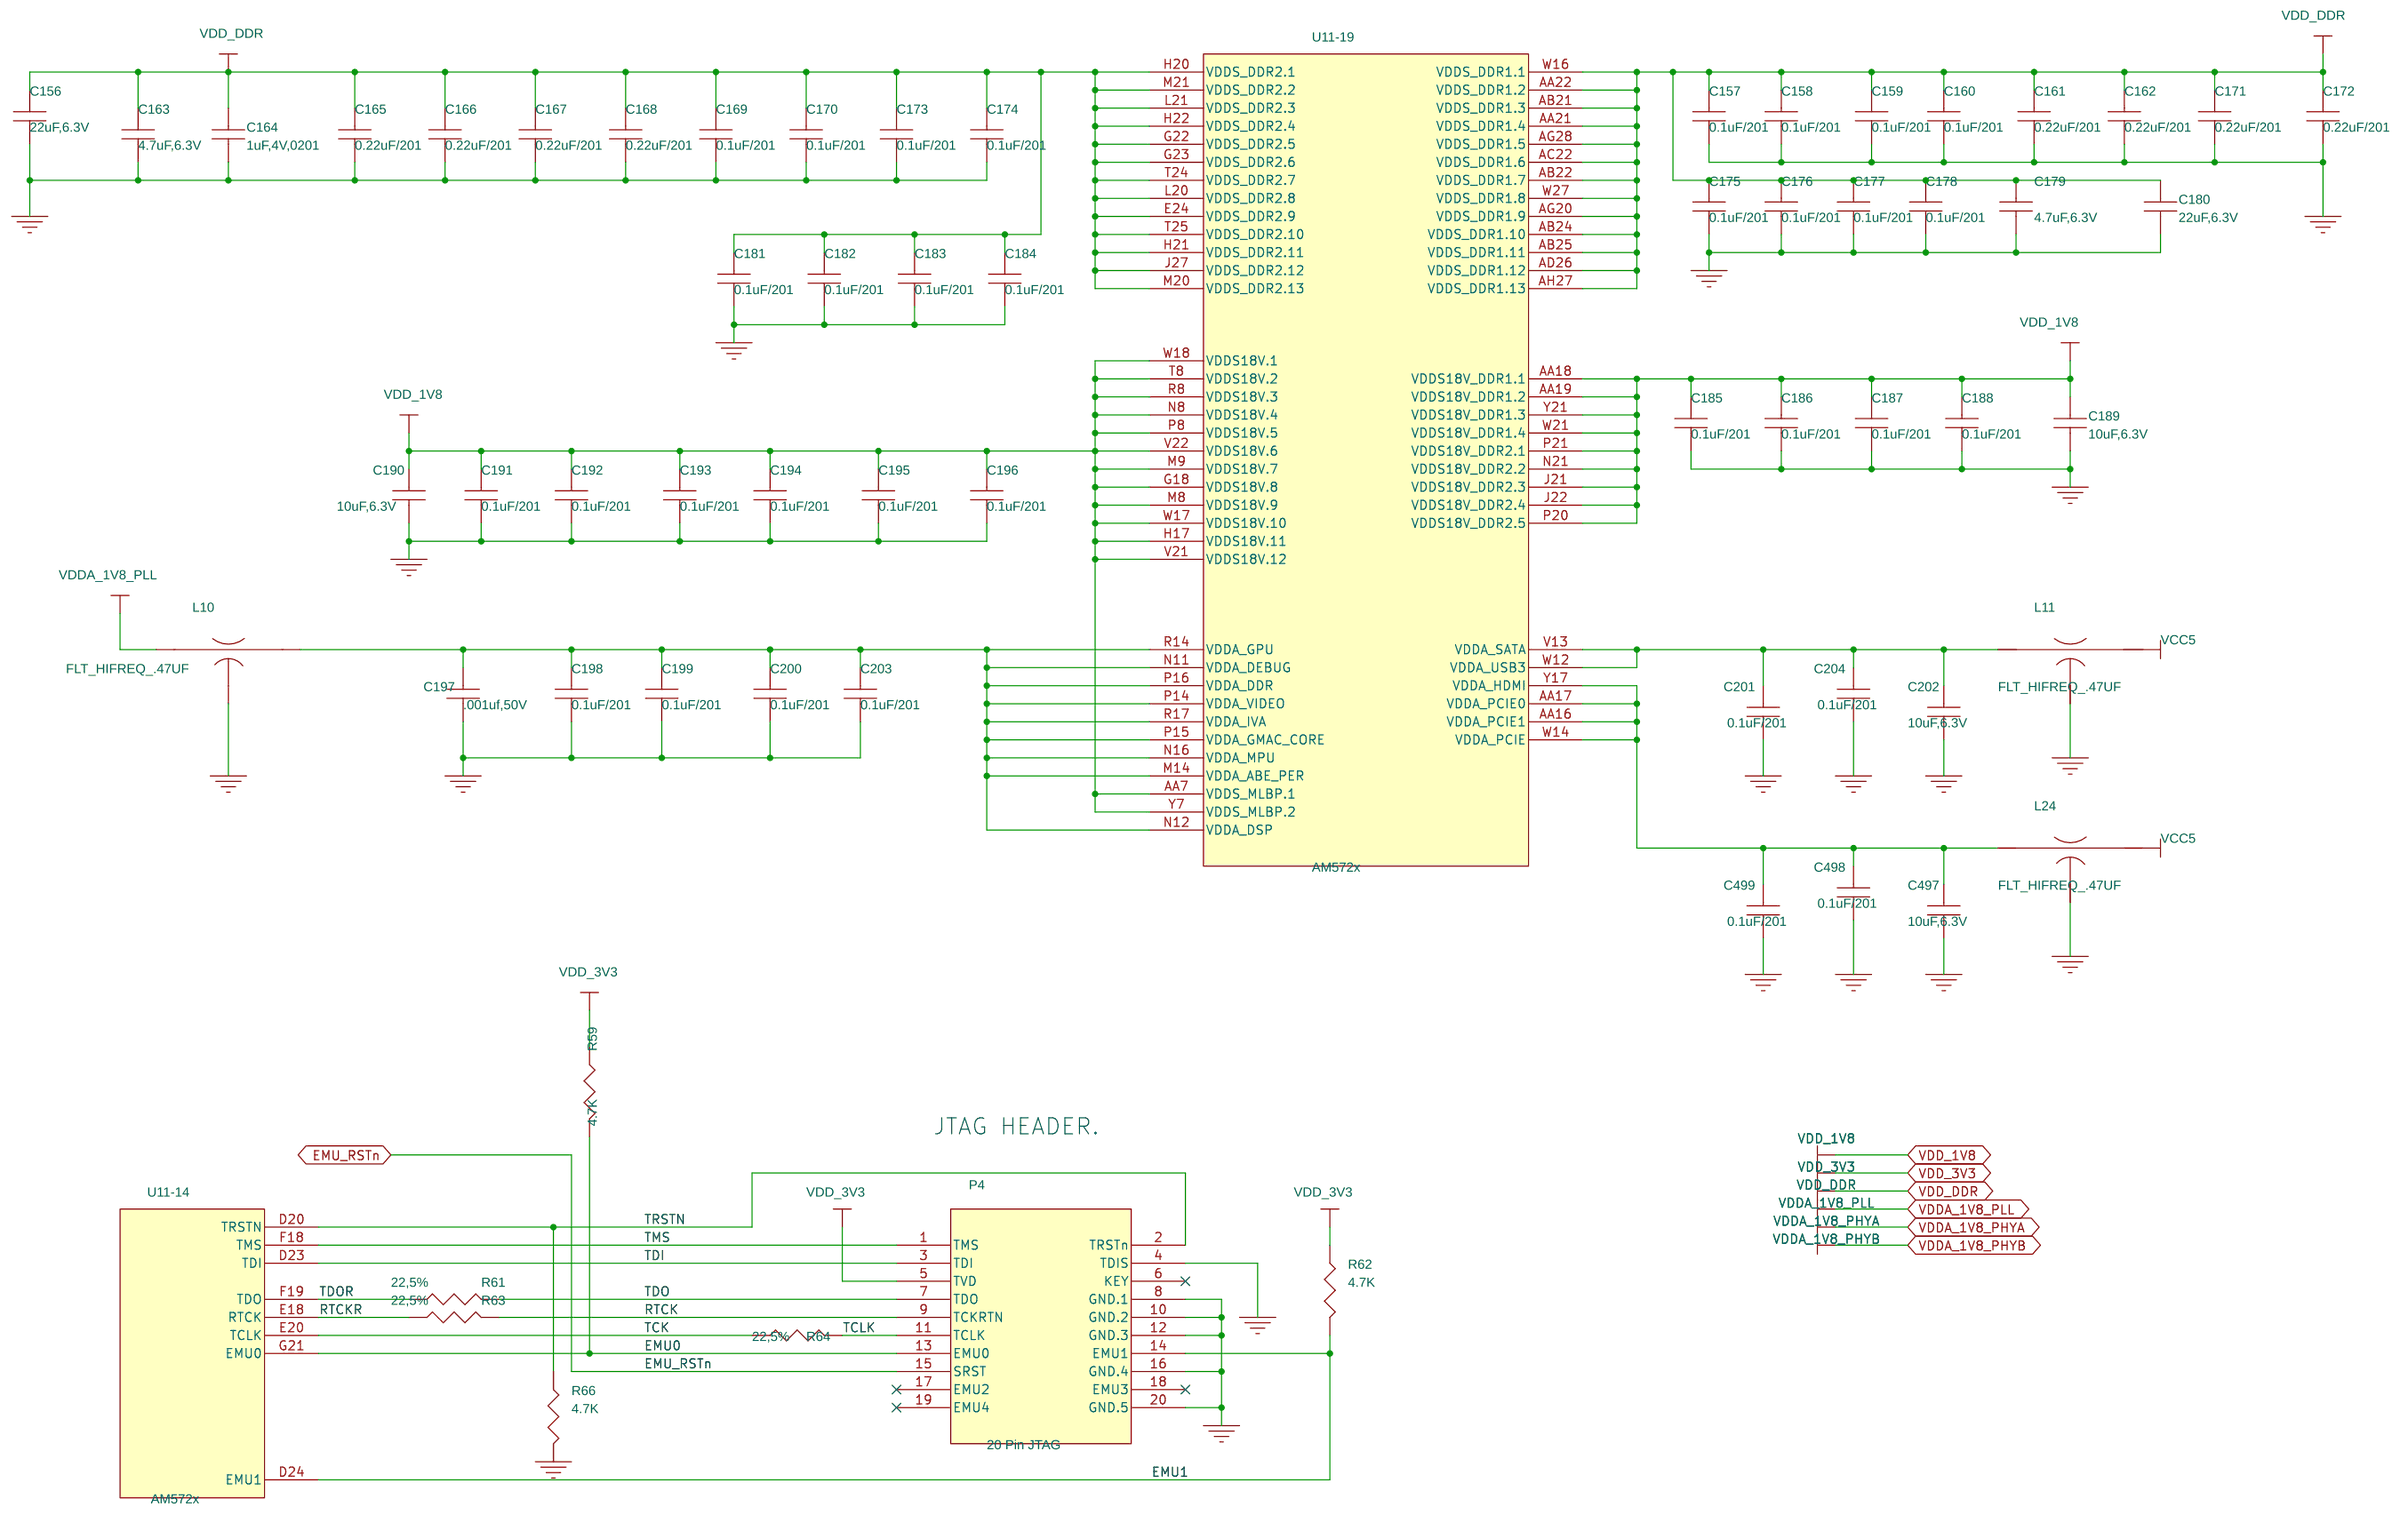
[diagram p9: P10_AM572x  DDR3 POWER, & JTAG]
11 P11_AM572x ETHERNET 0: size B
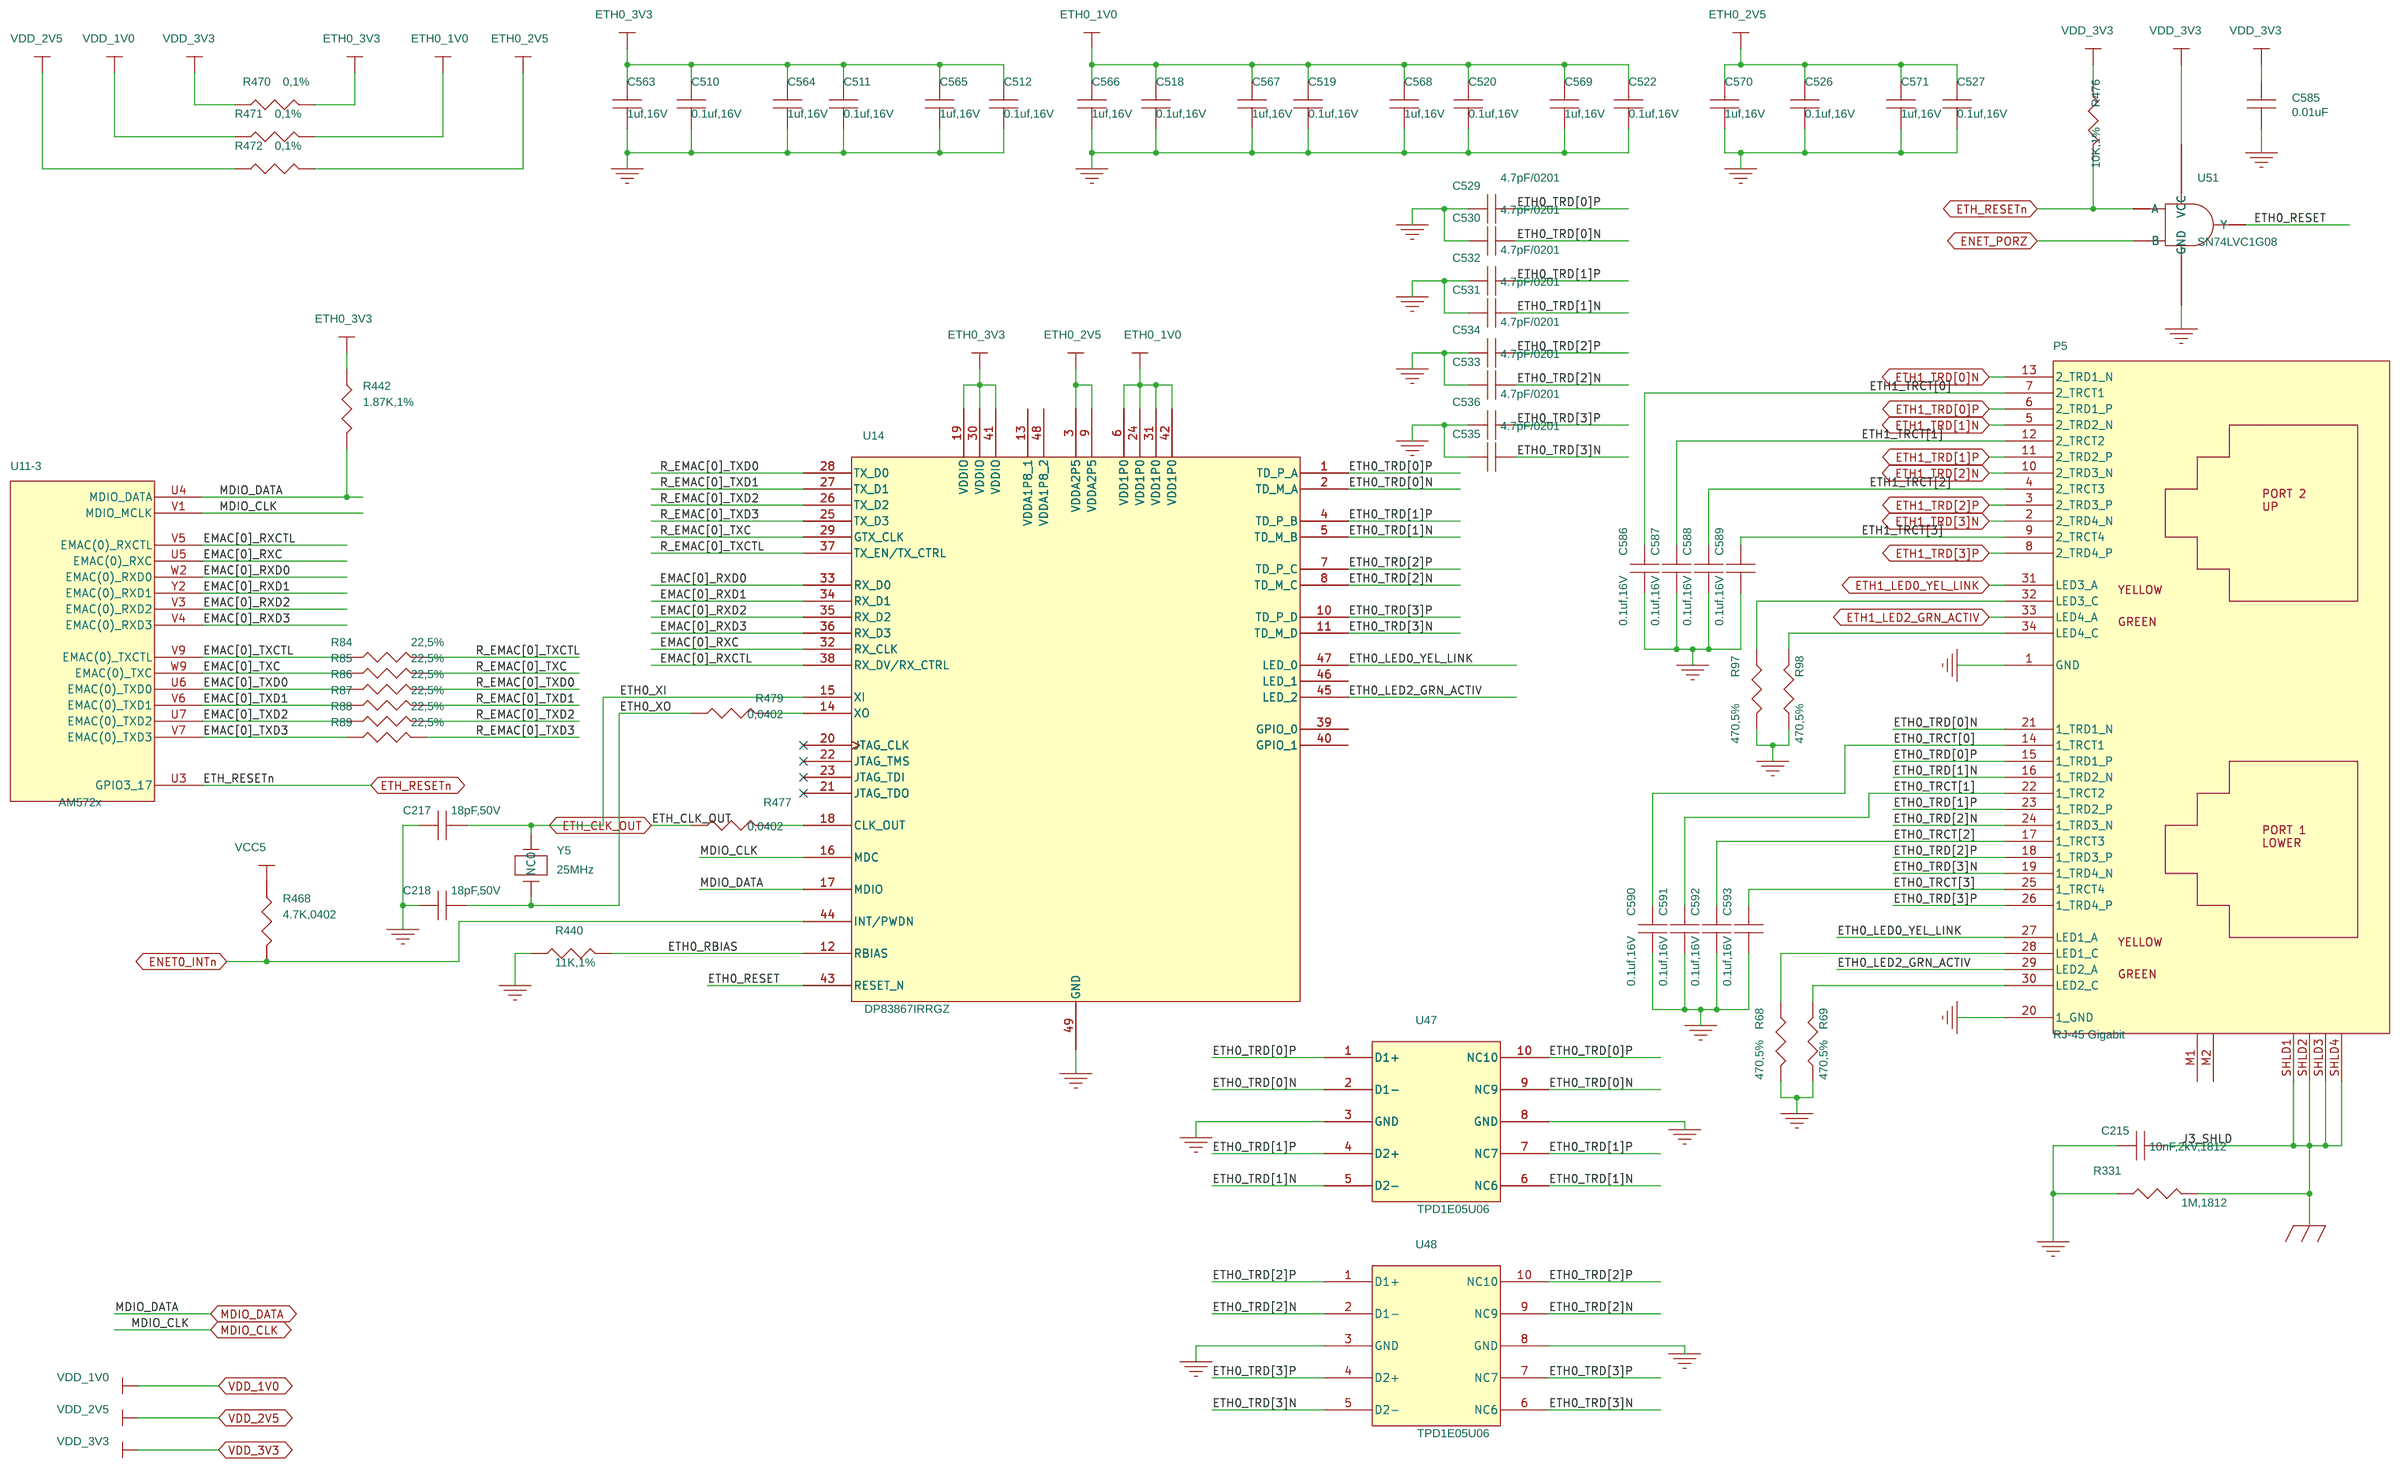
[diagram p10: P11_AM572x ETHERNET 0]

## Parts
sheet P02_12V IN, 3.3V & 5V SWITCHERS
C1  0.1uf,25V,0805  [805]
C2  100uF,10V  [6032]
C3  4.7uF,50V.LESR  [1210]
C4  8.2nF,10V,0201  [201]
C5  22pF  [402]
C6  .001uF,50V  [402]
C7  0.1uf,25V,0805  [805]
C8  100uF,10V  [6032]
C9  100uF,10V  [6032]
C10  220pF,50V  [805]
C11  820pF,50V  [805]
C12  15pF,50V  [805]
C13  8.2nF,10V,0201  [201]
C14  4.7uF,50V.LESR  [1210]
C15  0.1uf,16V  [402]
C49  47uF,6.3V,1206  [1206]
C438  4.7uF,50V.LESR  [1210]
C439  4.7uF,50V.LESR  [1210]
C443  470pF,6.3V  [402]
C445  4.7uF,50V.LESR  [1210]
C472  0.1uf,16V  [402]
C473  0.1uf,16V  [402]
C474  0.1uf,16V  [402]
C475  0.1uf,16V  [402]
D1  SK54AFL-TP  [DO221AC]
D2  SK54AFL-TP  [DO221AC]
D3  LTST-C191KFKT  [LED_603]
D41  LTST-C191KFKT  [LED_603]
F1  5A_SlowBlow  [FU250_200X400SMD]
J1  2POS 1.25MM  [CON2_49LS]
L1  4.7uH  [IND130_208X216]
L2  3.3uH,7A  [IND130_208X216]
MH1  MOUNT_HOLE  [MTGH250C125D_PL]
MH2  MOUNT_HOLE  [MTGH250C125D_PL]
MH3  MOUNT_HOLE  [MTGH250C125D_PL]
MH4  MOUNT_HOLE  [MTGH250C125D_PL]
MH5  MOUNT_HOLE  [MTGH200c102D_PL]
P1  CUI-PJ-080BH  [CNPJ-080BH]
P2  HDR_6x1_M_.1,DNI  [SIP6]
P3  HDR_6x1_M_.1,DNI  [SIP6]
R1  .01,1206  [1206]
R2  10.2K,1%  [402]
R3  169K  [402]
R4  45.3K  [402]
R5  1.91K  [402]
R6  20.5K,1%  [402]
R7  .01,1206  [1206]
R8  1K,5%  [402]
R9  169K  [402]
R10  10K,1%  [402]
R11  20.5K,1%  [402]
R12  51.1K  [402]
R13  10.2K,1%  [402]
R14  3.24K,1%  [402]
R15  4.7K  [402]
R240  3.24K,1%  [402]
R384  0,1%  [402]
R396  154K,1%  [402]
R397  470K,1%  [402]
R400  0,1%  [402]
R401  0,1%  [402]
R402  0,1%  [402]
R403  0,1%  [402]
R434  10K,1%,DNI  [402]
U1  TPS54531D  [DDA-8]
U2  TPS22965DSG  [WSON-8]
U3  TPS54531D  [DDA-8]
U4  TMP102AIDRLT  [SOT563]
U32  TL5209  [SO8-25X75]
sheet P03_TPS6590376 CONTROL
C16  0.1uf,16V  [402]
C216  0.1uf,16V  [402]
C452  16pF/0402/50V  [402]
C453  16pF/0402/50V  [402]
C478  0.1uf,16V  [402]
C496  2.2uF,6.3V  [402]
J5  HDR_1x1_M_.1,DNI  [SIP2]
R16  2.2K,1%  [402]
R17  2.2K,1%  [402]
R18  2.2K,1%  [402]
R19  2.2K,1%  [402]
R20  10K,DNI  [402]
R21  10K,1%  [402]
R22  10K,1%  [402]
R23  10K,1%,DNI  [402]
R24  10K,1%  [402]
R26  10K,1%  [402]
R27  10K,1%  [402]
R28  10K,1%  [402]
R29  0,1%  [402]
R30  0,1%  [402]
R214  10K,1%,DNI  [402]
R318  1.74K  [402]
R319  2K  [402]
R322  1.74K,DNI  [402]
R323  2K,DNI  [402]
R332  0,1%  [402]
R407  10K,1%  [402]
R411  10K,1%,DNI  [402]
R421  10K,1%  [402]
R433  10K,1%  [402]
S1  SW PUSH_TH  [SW4_EVQF004R]
TP5  TP  [TP30C12D]
TP7  TP  [TP30C12D]
TP8  TP  [TP30C12D]
TP9  TP  [TP30C12D]
Y9  16.384MHz  [XTAL4_3P2X2P5_SMD]
sheet P04_TPS6590376 2, LDO & RTC
BAT1  CR1220MFR FV,DNI  [BATT2_78X492]
C17  2.2uF,6.3V  [402]
C18  2.2uF,6.3V  [402]
C19  2.2uF,6.3V  [402]
C20  2.2uF,6.3V  [402]
C21  2.2uF,6.3V  [402]
C22  2.2uF,6.3V  [402]
C23  10uF,6.3V  [603]
C24  2.2uF,6.3V  [402]
C25  2.2uF,6.3V  [402]
C26  2.2uF,6.3V  [402]
C27  2.2uF,6.3V  [402]
C28  2.2uF,6.3V  [402]
C29  2.2uF,6.3V  [402]
C30  0.1uf,16V  [402]
C31  10pF,50V  [402]
C32  10pF,50V  [402]
C500  2.2uF,6.3V  [402]
Q8  TRN_2N2907  [SOT23-3]
Q9  TRN_2N2907  [SOT23-3]
R32  0,1%  [402]
R33  4.7K  [402]
R416  0,1%  [402]
R418  499,1%  [402]
R419  10K,1%  [402]
R420  40.2K,1%  [402]
R423  499,1%  [402]
R424  10K,1%  [402]
R425  40.2K,1%  [402]
R429  DNI  [402]
R430  DNI  [402]
U6  MCP79410,TFDN  [DFN8_2x3MM]
U35  TLVH431  [SOT23-3]
U43  TLVH431  [SOT23-3]
Y1  CFS-20632768DZBB  [XTAL_CFS-206]
sheet P05_TPS6590376 3 MPU,DSP SWITCH
C33  4.7uF,6.3V  [402]
C34  47uF,6.3V,1206  [1206]
C35  4.7uF,6.3V  [402]
C36  47uF,6.3V,1206  [1206]
C37  4.7uF,6.3V  [402]
C38  47uF,6.3V,1206  [1206]
C39  4.7uF,6.3V  [402]
C40  47uF,6.3V  [805]
C41  4.7uF,6.3V  [402]
C42  47uF,6.3V  [805]
L3  1.0uH,4.2A  [IND130_160X175]
L4  1.0uH,4.2A  [IND130_160X175]
L5  1.0uH,4.2A  [IND130_160X175]
L6  1.0uH,2.7A  [ind_1008]
L7  1.0uH,2.7A  [ind_1008]
R34  .01,1206  [1206]
R35  .01,1206  [1206]
TP13  TP  [TP30C12D]
TP16  TP  [TP30C12D]
TP17  TP  [TP30C12D]
sheet P06_TPS6590376 4 CORE & 1.8V
C43  4.7uF,6.3V  [402]
C44  47uF,6.3V  [805]
C45  4.7uF,6.3V  [402]
C46  4.7uF,6.3V  [402]
C47  47uF,6.3V,1206  [1206]
C48  4.7uF,6.3V  [402]
C50  10uF,6.3V  [603]
C442  10uF,6.3V  [603]
C583  47uF,6.3V  [805]
C584  47uF,6.3V  [805]
L8  1.0uH,2.7A  [ind_1008]
L9  1.0uH,4.2A  [IND130_160X175]
L25  1.0uH,2.7A  [ind_1008]
L26  1.0uH,2.7A  [ind_1008]
R36  .02,1206  [1206]
TP18  TP  [TP30C12D]
TP19  TP  [TP30C12D]
TP28  TP  [TP30C12D]
TP29  TP  [TP30C12D]
U5  TPS6590376ZWSR  [BGA169_N13_P8]  (sections A,B,C,D,E,F)
sheet P07_AM572x CORE POWER & EEPROM
C51  0.1uF/201  [201]
C52  0.22uF/201  [201]
C53  10uF,6.3V  [603]
C54  10uF,6.3V  [603]
C55  0.1uF/201  [201]
C56  0.22uF/201  [201]
C57  0.1uF/201  [201]
C58  0.1uF/201  [201]
C59  0.1uF/201  [201]
C60  0.1uF/201  [201]
C61  0.1uF/201  [201]
C62  0.1uF/201  [201]
C63  2.2uF,6.3V  [402]
C64  4.7uF,6.3V  [402]
C65  0.47uF/201  [201]
C66  0.1uF/201  [201]
C67  0.1uF/201  [201]
C68  0.1uF/201  [201]
C69  0.1uF/201  [201]
C70  4.7uF,6.3V  [402]
C71  0.1uF/201  [201]
C72  0.1uF/201  [201]
C73  0.1uF/201  [201]
C74  0.1uF/201  [201]
C75  0.1uF/201  [201]
C76  0.1uF/201  [201]
C77  0.1uF/201  [201]
C78  0.22uF/201  [201]
C79  0.47uF/201  [201]
C80  2.2uF,6.3V  [402]
C81  0.1uf,16V  [402]
C82  0.1uF/201  [201]
C83  0.1uF/201  [201]
C84  0.1uF/201  [201]
C85  0.1uF/201  [201]
C86  0.1uF/201  [201]
C87  0.1uF/201  [201]
C88  0.22uF/201  [201]
C89  0.22uF/201  [201]
C90  1uF,4V,0201  [201]
C91  1uF,4V,0201  [201]
C92  2.2uF,6.3V  [402]
C93  22uF,6.3V  [805]
R37  10K,1%,DNI  [402]
TP4  TESTPT1  [tp1-8040]
U8  MEM_24WC256_8SOIC  [SOIC_8]
sheet P08_AM572x CLOCKS & RESET
C94  0.1uf,16V  [402]
C95  0.1uF/201  [201]
C96  0.1uF/201  [201]
C97  0.1uf,16V  [402]
C98  0.1uF/201  [201]
C99  0.1uf,16V  [402]
C100  18pF,50V  [402]
C101  18pF,50V  [402]
C102  12pF,50V  [402]
C103  12pF,50V  [402]
C104  0.1uf,16V  [402]
C105  0.1uf,16V  [402]
C108  0.1uf,16V  [402]
C109  220pF,50V  [805]
C110  0.1uf,16V  [402]
C111  0.1uf,16V  [402]
C112  220pF,50V  [805]
C230  0.1uf,16V  [402]
C476  0.33uf,16V  [402]
R38  DNI,0402  [402]
R39  0,1%  [402]
R40  DNI,0402  [402]
R41  10K,1%  [402]
R42  10K,1%  [402]
R43  2.2K,1%  [402]
R44  10K,1%  [402]
R45  DNI,0402  [402]
R46  10K,1%  [402]
R47  DNI,0402  [402]
R48  100K,1%  [402]
R49  10K,1%,DNI  [402]
R50  10K,1%  [402]
R51  10K,1%  [402]
R52  10K,1%  [402]
R53  0,1%  [402]
R54  DNI,0402  [402]
R55  0,1%,DNI  [402]
R56  10K,1%  [402]
R57  0,1%  [402]
R58  10K,1%  [402]
R244  0,1%  [402]
R385  0,1%  [402]
R395  0,1%  [402]
R404  22.6K,1%  [402]
R405  10K,DNI  [402]
R422  0,1%  [402]
S2  SW PUSH_TH  [SW4_EVQF004R]
U9  SN74LVC1G11DBV  [SC70-6]
U10  SN74LVC1G08DCK  [SC70-5]
U12  TPS_3808G09  [sot23-6]
U13  TPS_3808G33  [sot23-6]
U34  SN74LVC2G132DCU  [U_8_DCU]  (sections A,B)
Y2  20MHz,SMD  [XTAL2_6X3P5_SMD]
Y3  22.5792MHZ  [XTAL4_3P2X2P5_SMD]
sheet P09 AM572x IO POWER & GND
C113  10uF,6.3V  [603]
C114  0.1uF/201  [201]
C115  0.1uF/201  [201]
C116  0.1uF/201  [201]
C117  0.1uF/201  [201]
C118  0.1uF/201  [201]
C119  0.1uF/201  [201]
C120  0.1uF/201  [201]
C121  0.1uF/201  [201]
C122  10uF,6.3V  [603]
C123  0.1uF/201  [201]
C124  0.1uF/201  [201]
C125  0.1uF/201  [201]
C126  0.1uF/201  [201]
C127  0.1uF/201  [201]
C128  0.1uF/201  [201]
C129  0.1uF/201  [201]
C130  10uF,6.3V  [603]
C131  10uF,6.3V  [603]
C132  0.1uF/201  [201]
C133  0.1uF/201  [201]
C134  0.1uF/201  [201]
C135  0.1uF/201  [201]
C136  0.1uF/201  [201]
C137  0.1uF/201  [201]
C138  0.1uF/201  [201]
C139  0.1uF/201  [201]
C140  0.1uF/201  [201]
C141  1uF,4V,0201  [201]
C142  1uF,4V,0201  [201]
C143  1uF,4V,0201  [201]
C144  1uF,4V,0201  [201]
C145  1uF,4V,0201  [201]
C146  1uF,4V,0201  [201]
C147  1uF,4V,0201  [201]
C148  1uF,4V,0201  [201]
C149  1uF,4V,0201  [201]
C150  1uF,4V,0201  [201]
C151  1uF,4V,0201  [201]
C152  1uF,4V,0201  [201]
C153  1uF,4V,0201  [201]
C154  1uF,4V,0201  [201]
C155  1uF,4V,0201  [201]
R417  220,5%  [402]
sheet P10_AM572x  DDR3 POWER, & JTAG
C156  22uF,6.3V  [805]
C157  0.1uF/201  [201]
C158  0.1uF/201  [201]
C159  0.1uF/201  [201]
C160  0.1uF/201  [201]
C161  0.22uF/201  [201]
C162  0.22uF/201  [201]
C163  4.7uF,6.3V  [402]
C164  1uF,4V,0201  [201]
C165  0.22uF/201  [201]
C166  0.22uF/201  [201]
C167  0.22uF/201  [201]
C168  0.22uF/201  [201]
C169  0.1uF/201  [201]
C170  0.1uF/201  [201]
C171  0.22uF/201  [201]
C172  0.22uF/201  [201]
C173  0.1uF/201  [201]
C174  0.1uF/201  [201]
C175  0.1uF/201  [201]
C176  0.1uF/201  [201]
C177  0.1uF/201  [201]
C178  0.1uF/201  [201]
C179  4.7uF,6.3V  [402]
C180  22uF,6.3V  [805]
C181  0.1uF/201  [201]
C182  0.1uF/201  [201]
C183  0.1uF/201  [201]
C184  0.1uF/201  [201]
C185  0.1uF/201  [201]
C186  0.1uF/201  [201]
C187  0.1uF/201  [201]
C188  0.1uF/201  [201]
C189  10uF,6.3V  [603]
C190  10uF,6.3V  [603]
C191  0.1uF/201  [201]
C192  0.1uF/201  [201]
C193  0.1uF/201  [201]
C194  0.1uF/201  [201]
C195  0.1uF/201  [201]
C196  0.1uF/201  [201]
C197  .001uf,50V  [402]
C198  0.1uF/201  [201]
C199  0.1uF/201  [201]
C200  0.1uF/201  [201]
C201  0.1uF/201  [201]
C202  10uF,6.3V  [603]
C203  0.1uF/201  [201]
C204  0.1uF/201  [201]
C497  10uF,6.3V  [603]
C498  0.1uF/201  [201]
C499  0.1uF/201  [201]
L10  FLT_HIFREQ_.47UF  [FLT3SMD_0805-2]
L11  FLT_HIFREQ_.47UF  [FLT3SMD_0805-2]
L24  FLT_HIFREQ_.47UF  [FLT3SMD_0805-2]
P4  20 Pin JTAG  [HEADER10X2_SMD]
R59  4.7K  [402]
R61  22,5%  [402]
R62  4.7K  [402]
R63  22,5%  [402]
R64  22,5%  [402]
R66  4.7K  [402]
sheet P11_AM572x ETHERNET 0
C215  10nF,2kV,1812  [1812]
C217  18pF,50V  [402]
C218  18pF,50V  [402]
C510  0.1uf,16V  [201]
C511  0.1uf,16V  [201]
C512  0.1uf,16V  [201]
C518  0.1uf,16V  [201]
C519  0.1uf,16V  [201]
C520  0.1uf,16V  [201]
C522  0.1uf,16V  [201]
C526  0.1uf,16V  [201]
C527  0.1uf,16V  [201]
C529  4.7pF/0201  [201]
C530  4.7pF/0201  [201]
C531  4.7pF/0201  [201]
C532  4.7pF/0201  [201]
C533  4.7pF/0201  [201]
C534  4.7pF/0201  [201]
C535  4.7pF/0201  [201]
C536  4.7pF/0201  [201]
C563  1uf,16V  [402]
C564  1uf,16V  [402]
C565  1uf,16V  [402]
C566  1uf,16V  [402]
C567  1uf,16V  [402]
C568  1uf,16V  [402]
C569  1uf,16V  [402]
C570  1uf,16V  [402]
C571  1uf,16V  [402]
C585  0.01uF  [402]
C586  0.1uf,16V  [201]
C587  0.1uf,16V  [201]
C588  0.1uf,16V  [201]
C589  0.1uf,16V  [201]
C590  0.1uf,16V  [201]
C591  0.1uf,16V  [201]
C592  0.1uf,16V  [201]
C593  0.1uf,16V  [201]
P5  RJ-45 Gigabit  [rj45_2x1_xfrm_led_new]
R68  470,5%  [402]
R69  470,5%  [402]
R84  22,5%  [402]
R85  22,5%  [402]
R86  22,5%  [402]
R87  22,5%  [402]
R88  22,5%  [402]
R89  22,5%  [402]
R97  470,5%  [402]
R98  470,5%  [402]
R331  1M,1812  [1812]
R440  11K,1%  [402]
R442  1.87K,1%  [402]
R468  4.7K,0402  [402]
R470  0,1%  [603]
R471  0,1%  [603]
R472  0,1%  [603]
R476  10K,1%  [402]
R477  0,0402  [402]
R479  0,0402  [402]
U11  AM572x  [sktbga-zkk-6334-p760]  (sections -1,-10,-11,-12,-13,-14,-15,-16,-17,-18,-19,-2,-3,-4,-5,-6,-7,-8,-9)
U14  DP83867IRRGZ  [QFN48_19-68_280X280_1]
U47  TPD1E05U06  [TPD4E05U06DQA]
U48  TPD1E05U06  [TPD4E05U06DQA]
U51  SN74LVC1G08  [sm-so-sc70-5]
Y5  25MHz  [xtal_3p2x5smd]

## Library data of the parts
C1 C7 = CAP_0.1uF_X7R_25V_10%_0805
C2 C8 C9 = CAP_100UF_TANT_6.3V_3528-21
C3 C14 C438 C439 C445 = CAP_4.7uF_X5R_50V_10%_LESR_1210
C4 C13 = CAP_8.2nF_X5R_10V_10%_0201
C5 = CAP
C6 = CAP_6.8nF_X7R_50V_10%_0805
C10 = CAP: Part #: 100993-1223R
C11 = CAP_820PF_X5R_50V_10%_0805
C12 = CAP_15PF_NPO_50V_5%_0805
C15 C16 C30 C81 C94 C97 C99 C104 C105 C108 C110 C111 C215 C216 C230 C472-C476 C478 C586-C593 = CAP_0.1uF_X7R_16V_10%_0402
C34 C36 C38 C47 C49 = CAP_47uF_X5R_6.3V_20%_1206
C443 = CAP_470PF_X7R_25V_10%_0402
D1 D2 = DIO_ZEN_DDZ9678-7_1.8V
D3 D41 = LED_LTST_C150GKT
F1 = FUSE_4A_QUICK
J1 J5 = HDR_1x1_M_.1
L1 L2 = INDUCTOR
MH1-MH5 = TESTPOINT
P1 = CONN_PWRJack_PJ-080BH
P2 P3 = HDR_5x2_M_2.1
R1 R7 R34-R36 = RES_0.002_1_2W_1%_0805
R2 R13 = RES_10.1K_1_16W_1%_0402
R3 R5 R9 R14 = RESISTOR
R4 R12 = RES_12.1K_1_16W_1%_0402
R6 R11 = RES_20.5K_1_16W_1%_0402
R8 R240 = RES_1K_1_16W_5%_0402
R10 R20-R24 R26 R27 R37 R41 R42 R44 R46 R49-R52 R56 R58 R214 R405 R407 R411 R419-R421 R424 R425 R429 R430 R433 R434 R476 = RES_10K_1_16W_1%_0402
R15 R33 = RES_4.75K_1_16W_1%_0402
R29 R30 R32 R39 R53 R57 R244 R384 R395 R416 R422 = RES_0_1_16W_1%_0402
R68 R69 R97 R98 R396 R397 = RES_470_1_10W_5%_0402
R331 R332 R385 R400-R403 = RES_1M_1_16W_1%_0402
U1 U3 = IC_TPS54331,3A_0
U2 = TPS22965DSG_1: Part #: 104267-0001R
U4 = IC_TMP102AIDRL_SOT563
U32 = PWR_TLV70233DBV_0
C452 C453 = C_12pF_0402_50V_COG_0402: Part #: 101782-1124R
C17-C22 C24-C29 C63 C80 C92 C496 C500 = CAP_2.2uF_X5R_6.3V_10%_0402
R16 R17 R43 = RES_2.2K_1_16W_1%_0402
R18 R19 R28 R38 R40 R45 R47 R54 R55 R318 R319 R322 R323 = RES_DNI_1_16W_1%_0402
S1 S2 = SW_PUSH_TH
TP5 TP7-TP9 TP13 TP16-TP19 TP28 TP29 = TP
Y9 = CRYS_24MHz_SCC
BAT1 = BATT_HOLD_BH501
C23 C50 C53 C54 C113 C122 C130 C131 C189 C190 C202 C442 C497 = CAP_10uF_X5R_6.3V_20%_0603
C31 C32 = CAP_10PF_COG_50V_5%_0402
Q8 Q9 = TRN_1
R418 R423 = RES_240_1_16W_1%_0402
U6 = IC_MCP79410
U35 U43 = MA735_TO_0
Y1 = CRYS_32_768KHz_SMD
C33 C35 C37 C39 C41 C43 C45 C46 C48 C64 C70 C163 C179 = CAP_4.7uF_X5R_6.3V_20%_0402
C40 C42 C44 C583 C584 = CAP_47uF_X5R_6.3V_20%_0805
L3-L5 L9 = IND_PWR_1.0uH_4.2A_SMD
L6-L8 L25 L26 = IND_PWR_1.0uH_2.7A_SMD
U5 = IC_TPS659039_8
C51 C55 C57-C62 C66-C69 C71-C77 C82-C87 C95 C96 C98 C114-C121 C123-C129 C132-C140 C157-C160 C169 C170 C173-C178 C181-C188 C191-C196 C198-C201 C203 C204 C498 C499 = CAP_0.1uF_X5R_6.3V_20%_0201
C52 C56 C78 C88 C89 C161 C162 C165-C168 C171 C172 = CAP_0.22uf_X5R_6.3V_20%_0201
C65 C79 = CAP_0.47UF_X5R_4V_20%_0201
C90 C91 C141-C155 C164 = CAP_1.0UF_X5R_4V_20%_0201
C93 C156 C180 = CAP_22uF_X5R_6.3V_20%_0805
TP4 = TESTPT1
U8 = MEM_24WC256_0
C100-C103 = CAP_18PF_COG_50V_5%_0402
C109 C112 = CAP_220PF_X7R_50V_10%_0402
R48 = RES_100K_1_16W_1%_0402
R404 = RES_22.6K_1_16W_1%_0402
U9 = IC_SN74LVC1G11_DRY
U10 = IC_SN74LVC1G08_DCK
U12 U13 = PWR_TPS3808G09DBVR_SOT23_0
U34 = IC_SN74LVC2G132DCU
Y2 = CRYS_20MHz_12.5pF_2P_3.2x1.5
Y3 = CRYS_22.5792MHz_7pF_4P_3.2x2.5
R417 = RES_220_1_16W_5%_0402
C197 = CAP_0.001_X7R_50V_10%_0402
L10 L11 L24 = FLT_HIFREQ_.47UF
P4 = HDR_JTAG_20P
R59 R62 R66 R468 = RES_4.7K_1_16W_5%_0402
R61 R63 R64 R84-R89 = RES_22_1_16W_5%_0402
C217 C218 = CAP_18PF_NPO_50V_5%_0402
C510-C512 C518-C520 C522 C526 C527 = CAP_0.1uF_X5R_16V_10%_0201
C529-C536 = CAP_4.7pF_C0G_50V_0201
C563-C571 = CAP_1uF_X6S_16V_10%_0402
C585 = 0.01uFCapacitor16V10%0402
P5 = CONN_RJ45_DUAL_GIGABIT_new
R440 R477 R479 = RES_11K_1_16W_1%_0402
R442 = RES_1.87K_1_16W_1%_0402
R470-R472 = RES_0_1_16W_1%_0603
U11 = IC_AM572x_BGA_36
U14 = DP83867IRRGZ_VQFN48: IC HIGH IMMUNITY 10/100/1000 Mb/s ETHERNET PHY LAYER TRANSCEIVER VQFN48; Chkd/date: MANIRAJA/110817; Crtd /date: MANIRAJA/110817; Custom_Duty: 15%; Customs_HS_Code: 85423100; Distributor_name: DIGIKEY; Distributor_part_number: DP83867IRRGZT-ND; Height: 1.00MM; Mfr_name: TEXAS INSTRUMENTS; Mistral Part No: 143017080002-R; Package: VQFN48; Part_type: ICS\TELECOM\TRANSCEIVER; Project: TI_SVB_CONTROLLER CARD; RoHS: RoHS; Temperature: -40°C+85°C; Tolerance: NA; Voltage: NA; Wattage: NA; Weight: NA; Datasheet: Y:\MIS_DATABASE\DATASHEETS\ICS\DIGITAL\BUSTRANSCEIVER\DP83867I.PDF
U47 U48 = TPD1E05U06
U51 = SN74LVC1G08DCKT_SC70
Y5 = CRYS_25MHz_18pF_2P_5.0x3.2

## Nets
3V3_RC: C11.2 R12.1
5V0: C17.2 C20.2 P3.4 R1.2 R2.1 U2.4(VBIAS) U5.A6(LDO12_IN) U5.A9(LDOUSB_IN2) U5.A10(LDO7USB_IN1) ; also on sheet 16 26 27
5V0_COMP: C5.2 R4.1 U1.6(COMP)
5V0_RC: C6.1 R4.2
5V0_SNS: R2.2 R5.2 U1.5(VSNS)
5V0_TAP: C2.1 L1.2 P2.4 R1.1
5V_FAN: C49.1 J1.1 R396.1 U32.3(OUT)
12V: C3.1 C14.1 C438.1 C439.1 C445.1 F1.2 R3.1 R9.1 R240.1 U1.2(VIN) U3.2(VIN) U32.2(IN) ; also on sheet 24 26
12V_MAIN: F1.1 P1.1
GND: BAT1.2(-) C2.2 C3.2 C4.2 C5.1 C6.2 C8.2 C9.2 C10.2 C12.2 C13.2 C14.2 C15.2 C16.1 C17.1 C18.1 C19.1 C20.1 C21.1 C22.1 C23.2 C24.1 C25.1 C26.1 C27.1 C28.1 C29.1 C30.2 C31.2 C32.2 C33.2 C34.2 C35.2 C36.2 C37.2 C38.2 C39.2 C40.2 C41.2 C42.2 C43.2 C44.2 C45.2 C46.2 C47.2 C48.2 C49.2 C50.2 C51.2 C52.1 C53.2 C54.2 C55.1 C56.1 C57.2 C58.1 C59.2 C60.1 C61.2 C62.1 C63.2 C64.2 C65.2 C66.1 C67.1 C68.2 C69.2 C70.2 C71.1 C72.1 C73.2 C74.2 C75.2 C76.2 C77.2 C78.1 C79.2 C80.2 C81.2 C82.2 C83.2 C84.2 C85.2 C86.2 C87.2 C88.1 C89.1 C90.2 C91.2 C92.1 C93.2 C94.2 C95.1 C96.1 C97.2 C98.1 C99.2 C104.2 C105.2 C108.2 C109.2 C110.2 C111.2 C112.2 C113.2 C114.2 C115.2 C116.2 C117.2 C118.2 C119.2 C120.2 C121.2 C122.2 C123.2 C124.2 C125.2 C126.2 C127.2 C128.2 C129.2 C130.2 C131.2 C132.2 C133.2 C134.2 C135.2 C136.2 C137.2 C138.2 C139.2 C140.2 C141.1 C142.2 C143.1 C144.2 C145.1 C146.2 C147.1 C148.2 C149.1 C150.2 C151.1 C152.2 C153.1 C154.2 C155.1 C156.2 C157.2 C158.2 C159.2 C160.2 C161.2 C162.2 C163.2 C164.2 C165.2 C166.2 C167.2 C168.2 C169.2 C170.2 C171.2 C172.2 C173.2 C174.2 C175.2 C176.2 C177.2 C178.2 C179.2 C180.2 C181.2 C182.2 C183.2 C184.2 C185.2 C186.2 C187.2 C188.2 C189.2 C190.2 C191.2 C192.2 C193.2 C194.2 C195.2 C196.2 C197.2 C198.2 C199.2 C200.2 C201.2 C202.2 C203.2 C204.2 C215.1 C216.1 C217.1 C218.1 C230.1 C438.2 C439.2 C442.2 C443.2 C445.2 C452.2 C453.2 C472.1 C473.1 C474.1 C475.1 C478.2 C496.2 C497.2 C498.2 C499.2 C500.1 C510.2 C511.2 C512.2 C518.2 C519.2 C520.2 C522.2 C526.2 C527.2 C529.1 C530.1 C531.1 C532.1 C533.1 C534.1 C535.1 C536.1 C563.2 C564.2 C565.2 C566.2 C567.2 C568.2 C569.2 C570.2 C571.2 C583.2 C584.2 C585.2 C586.2 C587.2 C588.2 C589.2 C590.2 C591.2 C592.2 C593.2 D1.2(ANODE) D2.2(ANODE) D3.1(C) D41.1(C) J1.2 L10.2 L11.2 L24.2 MH5.1(TP) P1.2 P1.SHLD1 P1.SHLD2 P1.SHLD3 P1.SHLD4 P2.6 P3.6 P4.4(TDIS) P4.8(GND.1) P4.10(GND.2) P4.12(GND.3) P4.16(GND.4) P4.20(GND.5) P5.1(GND) P5.20(1_GND) R5.1 R6.2 R11.2 R12.2 R14.1 R21.2 R22.2 R24.2 R26.2 R27.2 R28.1 R43.2 R47.2 R49.2 R50.2 R51.2 R54.1 R58.2 R66.2 R68.2 R69.1 R97.2 R98.1 R244.2 R319.1 R323.1 R331.1 R332.1 R384.2 R385.1 R395.2 R397.2 R400.1 R401.1 R402.1 R403.1 R404.2 R411.2 R416.2 R417.2 R421.2 R422.2 R434.2 R440.1 S1.1(A) S2.1(A) U1.7(GND) U1.9(PAD) U2.5(GND) U2.9(PWR_PAD) U3.7(GND) U3.9(PAD) U4.2(GND) U4.4(ADD0) U5.A1(SUB_GND) U5.A4(REFGND1) U5.A7(GNDANA) U5.A13(SUB_GND) U5.B2(GPADC_IN0) U5.B8(SYNC_TO_EXCLOCK) U5.B10(SUB_GND) U5.B11(SUB_GND) U5.C2(GPADC_IN1) U5.C3(GPADC_IN2) U5.C12(SMPS12_FBK_GND) U5.D4(SMPS7_GND_1) U5.D5(SMPS7_GND_2) U5.D6(SUB_GND) U5.D7(SUB_GND) U5.D10(SMPS1_GND_1) U5.E4(SMPS7_GND_3) U5.E7(VAC/ACOK) U5.E8(SUB_GND) U5.E9(SMPS1_GND_2) U5.E10(SMPS1_GND_3) U5.F4(SMPS4_GND_1) U5.F5(AGND.1) U5.F6(SUB_GND) U5.F7(SUB_GND) U5.F9(SMPS2_GND_1) U5.F10(SMPS2_GND_2) U5.G4(SMPS4_GND_2) U5.G5(SMPS4_GND_3) U5.G7(SUB_GND) U5.G10(SMPS2_GND_3) U5.H4(SMPS5_GND_1) U5.H5(SMPS5_GND_2) U5.H6(SUB_GND) U5.H7(SUB_GND) U5.H10(SMPS3_GND_1) U5.J4(SMPS5_GND_3) U5.J6(SUB_GND) U5.J9(SMPS3_GND_2) U5.J10(SMPS3_GND_3) U5.K3(SMPS45_FDBK_GND) U5.L5(SMPS6_GND) U5.L6(SMPS6_GND_1) U5.L7(SMPS9_GND) U5.L8(SMPS9_GND_1) U5.L9(SMPS8_GND_1) U5.L10(SMPS8_GND) U5.M1(SUB_GND) U5.M2(SUB_GND) U5.M12(GND_DIG) U5.M13(AGND.2) U5.N1(SUB_GND) U5.N2(VIO_GND) U5.N13(SUB_GND) U6.4(VSS) U8.1(A0) U8.2(A1) U8.3(NC) U8.4(VSS) U9.2(GND) U10.3(GND) U11.A1(VSS.9) U11.A2(VSS.11) U11.A6(VSS.15) U11.A14(VSS.41) U11.A23(VSS.68) U11.A28(VSS.79) U11.AA8(VSS.17) U11.AA9(VSS.19) U11.AA10(VSS.14) U11.AA14(VSS.48) U11.AA15(VSS.51) U11.AA20(VSS.61) U11.AB14(VSS.40) U11.AB20(VSS.60) U11.AD1(VSS.3) U11.AD24(VSS.70) U11.AG1(VSS.2) U11.AH1(VSS.1) U11.AH2(VSS.10) U11.AH8(VSS.53) U11.AH20(VSS.52) U11.AH28(VSS.75) U11.B1(VSS.8) U11.D13(VSS.39) U11.D19(VSS.59) U11.E13(VSS.38) U11.E19(VSS.58) U11.F1(VSS.7) U11.F7(VSS.54) U11.G7(VSS.57) U11.G8(VSS.65) U11.G9(VSS.66) U11.H12(VSS.33) U11.J12(VSS.32) U11.J15(VSS.XX) U11.J28(VSS.78) U11.K1(VSS.6) U11.K4(VSS.12) U11.K5(VSS.13) U11.K15(VSS.28) U11.K24(VSS.55) U11.K25(VSS.56) U11.L13(VSS.37) U11.L14(VSS.46) U11.M19(VSS.69) U11.N14(VSS.X5) U11.N15(VSS.16) U11.N19(VSS.18) U11.N24(VSS.72) U11.N25(VSS.74) U11.P28(VSS.77) U11.R1(VSS.5) U11.R12(VSS.29) U11.R13(VSS.X6) U11.R15(VSS.43) U11.R21(VSS.64) U11.T10(VSS.21) U11.T11(VSS.26) U11.T12(VSS.23) U11.T14(VSS.X7) U11.T15(VSS.42) U11.T17(VSS.47) U11.T18(VSS.24) U11.T21(VSS.27) U11.U14(VSSA_VIDEO) U11.U15(VSS.X8) U11.U17(VSS.X9) U11.U20(VSS.62) U11.U21(VSS.63) U11.V15(VSS.30) U11.V17(VSS.X10) U11.W1(VSS.4) U11.W15(VSS.36) U11.W24(VSS.71) U11.W25(VSS.73) U11.W28(VSS.76) U12.2(GND) U13.2(GND) U14.49(GND) U32.5(GND1) U32.6(GND3) U32.7(GND2) U32.8(GND4) U34.4(GND) U47.3(GND) U47.8(GND) U48.3(GND) U48.8(GND) U51.3(GND) Y9.2(NC0) Y9.4(NC1) ; also on sheet 12 13 14 15 16 17 18 19 20 21 22 23 24 25 26 27
GND_EARTH: C215.2 C216.2 C230.2 C472.2 C473.2 C474.2 C475.2 MH1.1(TP) MH2.1(TP) MH3.1(TP) MH4.1(TP) P5.SHLD1 P5.SHLD2 P5.SHLD3 P5.SHLD4 R331.2 R332.2 R384.1 R385.2 R400.2 R401.2 R402.2 R403.2 S1.3(B) S1.4(BB) S2.3(B) S2.4(BB) ; also on sheet 14 15 16 24
VCC_SENSE: R30.2 U5.B3(VCC_SENSE)
VCC_SENSE2: R29.2 U5.A11(VCC_SENSE2)
VDD_1V0: C583.1 L25.2 R471.1 TP28.1 U5.J8(SMPS9_FBK) ; also on sheet 12
VDD_1V8: C47.1 C185.1 C186.1 C187.1 C188.1 C189.1 C190.1 C191.1 C192.1 C193.1 C194.1 C195.1 C196.1 L9.2 Q8.3(COLLECTOR) Q9.3(COLLECTOR) R420.2 R425.2 TP19.1 U5.L11(SMPS8_FDBK) U11.AA7(VDDS_MLBP.1) U11.AA18(VDDS18V_DDR1.1) U11.AA19(VDDS18V_DDR1.2) U11.G18(VDDS18V.8) U11.H17(VDDS18V.11) U11.J21(VDDS18V_DDR2.3) U11.J22(VDDS18V_DDR2.4) U11.M8(VDDS18V.9) U11.M9(VDDS18V.7) U11.N8(VDDS18V.4) U11.N21(VDDS18V_DDR2.2) U11.P8(VDDS18V.5) U11.P20(VDDS18V_DDR2.5) U11.P21(VDDS18V_DDR2.1) U11.R8(VDDS18V.3) U11.T8(VDDS18V.2) U11.V21(VDDS18V.12) U11.V22(VDDS18V.6) U11.W17(VDDS18V.10) U11.W18(VDDS18V.1) U11.W21(VDDS18V_DDR1.4) U11.Y7(VDDS_MLBP.2) U11.Y21(VDDS18V_DDR1.3) U35.3(ANODE) U43.3(ANODE) ; also on sheet 25
VDD_2V5: C584.1 L26.2 R472.1 TP29.1 U5.B1(SMPS7_FDBK) ; also on sheet 12
VDD_3V3: C15.1 C30.1 C50.1 C81.1 C113.1 C114.1 C115.1 C116.1 C117.1 C118.1 C119.1 C120.1 C121.1 C122.1 C123.1 C124.1 C125.1 C126.1 C127.1 C128.1 C129.1 C130.1 C131.1 C132.1 C133.1 C134.1 C135.1 C136.1 C137.1 C138.1 C139.1 C585.1 P4.5(TVD) Q8.2(EMITTER) R8.1 R15.1 R16.1 R17.1 R18.2 R19.2 R32.1 R33.1 R37.2 R38.2 R45.1 R46.1 R48.1 R59.1 R62.1 R418.1 R419.1 R470.1 R476.1 U2.7(VOUT.2) U2.8(VOUT.1) U4.5(V+) U5.D9(VIO_IN) U6.8(VCC) U8.8(VCC) U11.AB6(VDDSHV7.1) U11.AB7(VDDSHV7.2) U11.AD5(VDDSHV6.2) U11.AD7(VDDSHV6.4) U11.AE7(VDDSHV6.3) U11.AF5(VDDSHV6.1) U11.B6(VDDSHV2.1) U11.B23(VDDSHV3.9) U11.C24(VDDSHV4.1) U11.D10(VDDSHV2.5) U11.D16(VDDSHV3.4) U11.D22(VDDSHV3.8) U11.E3(VDDSHV1.1) U11.E5(VDDSHV1.4) U11.E10(VDDSHV2.4) U11.E16(VDDSHV3.3) U11.E22(VDDSHV3.7) U11.G4(VDDSHV1.2) U11.G5(VDDSHV1.3) U11.G15(VDDSHV3.2) U11.H8(VDDSHV1.5) U11.H9(VDDSHV1.6) U11.H10(VDDSHV2.2) U11.H11(VDDSHV2.3) U11.H15(VDDSHV3.1) U11.H16(VDDSHV3.6) U11.H18(VDDSHV3.5) U11.H19(VDDSHV3.10) U11.J8(VDDSHV11.2) U11.K8(VDDSHV11.1) U11.N4(VDDSHV10.2) U11.N5(VDDSHV10.4) U11.P10(VDDSHV10.6) U11.R7(VDDSHV10.5) U11.R10(VDDSHV10.7) U11.T4(VDDSHV10.1) U11.T5(VDDSHV10.3) U11.U10(VDDSHV9.3) U11.W4(VDDSHV9.1) U11.W5(VDDSHV9.2) U51.5(VCC) ; also on sheet 12 13 14 15 16 17 23 24 25 26 27
VDD_3V3_ON: R10.2 R434.1 U2.3(ON) U5.F8(REGEN1)
VDD_3V3_SP: C94.1 C97.1 C104.1 R32.2 R41.1 R42.1 R44.1 R52.1 R405.1 U9.5(VCC) U10.5(VCC) U12.6(VDD) U34.8(VCC)
VDD_CORE: C54.1 C55.2 C56.2 C58.2 C60.2 C62.2 C65.1 C66.2 C67.2 C71.2 C72.2 P3.3 R36.2 TP18.1 U5.K6(SMPS6_FBK) U11.H13(VDD.18) U11.H14(VDD.22) U11.J17(VDD.X1) U11.J18(VDD.X2) U11.L7(VDD.34) U11.L8(VDD.15) U11.N10(VDD.6) U11.N13(VDD.16) U11.P11(VDD.9) U11.P12(VDD.12) U11.P13(VDD.X3) U11.R11(VDD.8) U11.R16(VDD.26) U11.R19(VDD.27) U11.T13(VDD.13) U11.T16(VDD.25) U11.T19(VDD.X7) U11.U8(VDD.29) U11.U9(VDD.2) U11.U13(VDD.3) U11.U16(VDD.X8) U11.V8(VDD.1) U11.V16(VDD.X9)
VDD_DDR: C38.1 C156.1 C157.1 C158.1 C159.1 C160.1 C161.1 C162.1 C163.1 C164.1 C165.1 C166.1 C167.1 C168.1 C169.1 C170.1 C171.1 C172.1 C173.1 C174.1 C175.1 C176.1 C177.1 C178.1 C179.1 C180.1 C181.1 C182.1 C183.1 C184.1 L5.2 TP16.1 U5.K13(SMPS3_FDBK) U11.AA21(VDDS_DDR1.4) U11.AA22(VDDS_DDR1.2) U11.AB21(VDDS_DDR1.3) U11.AB22(VDDS_DDR1.7) U11.AB24(VDDS_DDR1.10) U11.AB25(VDDS_DDR1.11) U11.AC22(VDDS_DDR1.6) U11.AD26(VDDS_DDR1.12) U11.AG20(VDDS_DDR1.9) U11.AG28(VDDS_DDR1.5) U11.AH27(VDDS_DDR1.13) U11.E24(VDDS_DDR2.9) U11.G22(VDDS_DDR2.5) U11.G23(VDDS_DDR2.6) U11.H20(VDDS_DDR2.1) U11.H21(VDDS_DDR2.11) U11.H22(VDDS_DDR2.4) U11.J27(VDDS_DDR2.12) U11.L20(VDDS_DDR2.8) U11.L21(VDDS_DDR2.3) U11.M20(VDDS_DDR2.13) U11.M21(VDDS_DDR2.2) U11.T24(VDDS_DDR2.7) U11.T25(VDDS_DDR2.10) U11.W16(VDDS_DDR1.1) U11.W27(VDDS_DDR1.8) ; also on sheet 18 20 21 22 23
VDD_DSP: C51.1 C52.2 C53.1 C57.1 C59.1 C61.1 C63.1 C64.1 C68.1 C69.1 C70.1 C73.1 C74.1 C75.1 C76.1 C78.2 C79.1 C80.1 P3.2 R35.2 TP17.1 U5.K2(SMPS45_FDBK) U11.J13(VDD_DSP.7) U11.K10(VDD_DSP.8) U11.K11(VDD_DSP.9) U11.K12(VDD_DSP.10) U11.K13(VDD_DSP.11) U11.L10(VDD_DSP.2) U11.L11(VDD_DSP.4) U11.L12(VDD_DSP.12) U11.M10(VDD_DSP.1) U11.M11(VDD_DSP.5) U11.M12(VDD_DSP.3) U11.M13(VDD_DSP.6) U11.U11(VDD_GPU.5) U11.U12(VDD_GPU.6) U11.U18(VDD_IVA.1[ECO]) U11.U19(VDD_IVA.2[ECO]) U11.V10(VDD_GPU.2) U11.V11(VDD_GPU.3) U11.V14(VDD_GPU.7) U11.V18(VDD_IVA.3[ECO]) U11.V19(VDD_IVA.4[ECO]) U11.W10(VDD_GPU.1) U11.W11(VDD_GPU.4) U11.W13(VDD_GPU.8)
VDD_MPU: C77.1 C82.1 C83.1 C84.1 C85.1 C86.1 C87.1 C88.2 C89.2 C90.1 C91.1 C92.2 C93.1 P3.5 R34.2 R54.2 TP13.1 U5.B13(SMPS12_FBK) U11.K17(VDD_MPU.10) U11.K18(VDD_MPU.2) U11.L15(VDD_MPU.11) U11.L16(VDD_MPU.12) U11.L17(VDD_MPU.6) U11.L18(VDD_MPU.8) U11.L19(VDD_MPU.3) U11.M15(VDD_MPU.13) U11.M16(VDD_MPU.14) U11.M17(VDD_MPU.5) U11.M18(VDD_MPU.7) U11.N17(VDD_MPU.4) U11.N18(VDD_MPU.1) U11.P17(VDD_MPU.15) U11.P18(VDD_MPU.9) U11.R18(VDD_MPU.16) U12.5(SENSE1)
VDD_RTC: C28.2 C108.1 U5.A5(LDO9_OUT) U11.AB15(VDD_RTC)
VDD_SD: C21.2 C140.1 U5.C6(LDO1_OUT) U11.W8(VDDSHV8.2) U11.Y8(VDDSHV8.1) ; also on sheet 17
VDD_SHV5: C22.2 C105.1 Q9.2(EMITTER) R423.1 R424.1 U5.B6(LDO2_OUT) U11.V12(VDDSHV5)
VDDA_1V8_PHYA: C24.2 L11.3 U5.K11(LDO3_OUT) ; also on sheet 14
VDDA_1V8_PHYB: C500.2 L24.3 U5.K12(LDO4_OUT)
VDDA_1V8_PLL: C29.2 C99.1 L10.1 U5.B5(LDOLN_OUT) U11.AD16(VDDA_OSC.1) U11.AE16(VDDA_OSC.2)
VSSA_OSC0: C100.2 C101.2 R244.1 U11.AF15(VSSA_OSC0)
VSSA_OSC1: C102.2 C103.2 R395.1 U11.AC14(VSSA_OSC1) Y3.2(NC0) Y3.4(NC1)
AM_CAP0: C141.2 U11.Y15(CAP_VDDRAM_CORE3)
AM_CAP1: C143.2 U11.J19(CAP_VDDRAM_CORE2)
AM_CAP2: C145.2 U11.P19(CAP_VDDRAM_CORE4)
AM_CAP3: C147.2 U11.Y16(CAP_VDDRAM_CORE5)
AM_CAP4: C149.2 U11.K9(CAP_VBBLDO_DSP)
AM_CAP5: C151.2 U11.J9(CAP_VDDRAM_DSP2)
AM_CAP6: C153.2 U11.K19(CAP_VDDRAM_MPU2)
AM_CAP7: C155.2 U11.L9(CAP_VDDRAM_CORE1)
AM_CAP8: C142.1 U11.R20(CAP_VBBLDO_IVA)
AM_CAP9: C144.1 U11.Y14(CAP_VBBLDO_GPU)
AM_CAP10: C146.1 U11.J16(CAP_VBBLDO_MPU)
AM_CAP11: C148.1 U11.J10(CAP_VDDRAM_DSP)
AM_CAP12: C150.1 U11.T20(CAP_VDDRAM_IVA)
AM_CAP13: C152.1 U11.Y13(CAP_VDDRAM_GPU)
AM_CAP14: C154.1 R417.1 U11.K16(CAP_VDDRAM_MPU1)
AUXFAN_EN: R24.1 U5.A12(GPIO_2/REGEN2) U32.1(EN)
BU_BATT: BAT1.1(+) R416.1 U6.3(VBAT)
CPU_NMIn: R46.2 R47.1 U11.D21(NMIN)
CPU_POR_RESETn: R41.2 R53.2 U9.6(C)
CPU_RESETn: R42.2 R55.1 U10.1(B)
EEWP: R37.1 TP4.1(TP) U8.7(WP)
EMAC[0]_RXC: U11.U5(EMAC(0)_RXC) U14.32(RX_CLK)
EMAC[0]_RXCTL: U11.V5(EMAC(0)_RXCTL) U14.38(RX_DV/RX_CTRL)
EMAC[0]_RXD0: U11.W2(EMAC(0)_RXD0) U14.33(RX_D0)
EMAC[0]_RXD1: U11.Y2(EMAC(0)_RXD1) U14.34(RX_D1)
EMAC[0]_RXD2: U11.V3(EMAC(0)_RXD2) U14.35(RX_D2)
EMAC[0]_RXD3: U11.V4(EMAC(0)_RXD3) U14.36(RX_D3)
EMAC[0]_TXC: R85.1 U11.W9(EMAC(0)_TXC)
EMAC[0]_TXCTL: R84.1 U11.V9(EMAC(0)_TXCTL)
EMAC[0]_TXD0: R86.1 U11.U6(EMAC(0)_TXD0)
EMAC[0]_TXD1: R87.1 U11.V6(EMAC(0)_TXD1)
EMAC[0]_TXD2: R88.1 U11.U7(EMAC(0)_TXD2)
EMAC[0]_TXD3: R89.1 U11.V7(EMAC(0)_TXD3)
EMU0: P4.13(EMU0) R59.2 U11.G21(EMU0)
EMU1: P4.14(EMU1) R62.2 U11.D24(EMU1)
EMU_RSTn: P4.15(SRST) R44.2 U10.2(A)
ENET0_INTn: R468.2 U14.44(INT/PWDN) ; also on sheet 27
ENET_PORZ: R39.2 R40.2 U51.2(B) ; also on sheet 12
ETH0_1V0: C518.1 C519.1 C520.1 C522.1 C566.1 C567.1 C568.1 C569.1 R471.2 U14.6(VDD1P0) U14.24(VDD1P0) U14.31(VDD1P0) U14.42(VDD1P0)
ETH0_2V5: C526.1 C527.1 C570.1 C571.1 R472.2 U14.3(VDDA2P5) U14.9(VDDA2P5)
ETH0_3V3: C510.1 C511.1 C512.1 C563.1 C564.1 C565.1 R442.1 R468.1 R470.2 U14.19(VDDIO) U14.30(VDDIO) U14.41(VDDIO)
ETH0_LED0_YEL_LINK: P5.27(LED1_A) U14.47(LED_0)
ETH0_LED2_GRN_ACTIV: P5.29(LED2_A) U14.45(LED_2)
ETH0_RBIAS: R440.2 U14.12(RBIAS)
ETH0_RESET: U14.43(RESET_N) U51.4(Y)
ETH0_TRCT[0]: C590.1 P5.14(1_TRCT1)
ETH0_TRCT[1]: C591.1 P5.22(1_TRCT2)
ETH0_TRCT[2]: C592.1 P5.17(1_TRCT3)
ETH0_TRCT[3]: C593.1 P5.25(1_TRCT4)
ETH0_TRD[0]N: C530.2 P5.21(1_TRD1_N) U14.2(TD_M_A) U47.2(D1-) U47.9(NC9)
ETH0_TRD[0]P: C529.2 P5.15(1_TRD1_P) U14.1(TD_P_A) U47.1(D1+) U47.10(NC10)
ETH0_TRD[1]N: C531.2 P5.16(1_TRD2_N) U14.5(TD_M_B) U47.5(D2-) U47.6(NC6)
ETH0_TRD[1]P: C532.2 P5.23(1_TRD2_P) U14.4(TD_P_B) U47.4(D2+) U47.7(NC7)
ETH0_TRD[2]N: C533.2 P5.24(1_TRD3_N) U14.8(TD_M_C) U48.2(D1-) U48.9(NC9)
ETH0_TRD[2]P: C534.2 P5.18(1_TRD3_P) U14.7(TD_P_C) U48.1(D1+) U48.10(NC10)
ETH0_TRD[3]N: C535.2 P5.19(1_TRD4_N) U14.11(TD_M_D) U48.5(D2-) U48.6(NC6)
ETH0_TRD[3]P: C536.2 P5.26(1_TRD4_P) U14.10(TD_P_D) U48.4(D2+) U48.7(NC7)
ETH0_XI: C217.2 U14.15(XI) Y5.2(NC0)
ETH0_XO: C218.2 R479.1 Y5.1
ETH1_LED0_YEL_LINK: P5.31(LED3_A) ; also on sheet 12
ETH1_LED2_GRN_ACTIV: P5.33(LED4_A) ; also on sheet 12
ETH1_TRCT[0]: C586.1 P5.7(2_TRCT1)
ETH1_TRCT[1]: C587.1 P5.12(2_TRCT2)
ETH1_TRCT[2]: C588.1 P5.4(2_TRCT3)
ETH1_TRCT[3]: C589.1 P5.9(2_TRCT4)
ETH1_TRD[0]N: P5.13(2_TRD1_N) ; also on sheet 12
ETH1_TRD[0]P: P5.6(2_TRD1_P) ; also on sheet 12
ETH1_TRD[1]N: P5.5(2_TRD2_N) ; also on sheet 12
ETH1_TRD[1]P: P5.11(2_TRD2_P) ; also on sheet 12
ETH1_TRD[2]N: P5.10(2_TRD3_N) ; also on sheet 12
ETH1_TRD[2]P: P5.3(2_TRD3_P) ; also on sheet 12
ETH1_TRD[3]N: P5.2(2_TRD4_N) ; also on sheet 12
ETH1_TRD[3]P: P5.8(2_TRD4_P) ; also on sheet 12
ETH_CLK_OUT: R477.1 ; also on sheet 12
ETH_RESETn: R476.2 U11.U3(GPIO3_17) U51.1(A)
EXT_WAKE: R33.2 R49.1 U6.7(MFP) U11.AC16(WAKEUP3) ; also on sheet 26
I2C1_SCL: R17.2 U4.1(SCL) U5.L1(I2C1_SCL_SCK) U8.6(SCL) ; also on sheet 15 27
I2C1_SDA: R16.2 U4.6(SDA) U5.L2(I2C1_SDA_SDI) U8.5(SDA) ; also on sheet 15 27
I2C3_SCL: U6.6(SCL) ; also on sheet 14 27
I2C3_SDA: U6.5(SDA) ; also on sheet 14 27
LDO_VRTC: C19.2 C110.1 J5.2 R20.2 R23.1 R56.1 R214.2 R433.2 U5.A8(LDOVRTC_OUT) U11.AB13(VDDA_RTC)
MDIO_CLK: U11.V1(MDIO_MCLK) U14.16(MDC) ; also on sheet 12
MDIO_DATA: R442.2 U11.U4(MDIO_DATA) U14.17(MDIO) ; also on sheet 12
OSC0_XI: C101.1 U11.AE15(XI_OSC0) Y2.1
OSC0_XO: C100.1 U11.AD15(X0_OSC0) Y2.2(NC0)
OSC1_XI: C103.1 U11.AC15(XI_OSC1) Y3.1
OSC1_XO: C102.1 U11.AC13(XO_OSC1) Y3.3
PMIC_BOOT0: R20.1 R21.1 U5.L3(BOOT0)
PMIC_BOOT1: R22.1 R214.1 U5.K7(BOOT1)
PMIC_GPIO_0: R421.1 U5.B12(GPIO_0)
PMIC_GPIO_3: R26.1 U5.H9(GPIO_3)
PMIC_GPIO_5: R27.1 U5.C10(GPIO_5/CLK32KGO)
PMIC_INT: R48.2 U5.K1(INT) U11.AD17(WAKEUP0)
PMIC_OFF: R45.2 R322.1 U11.Y11(ON_OFF)
PMIC_POWERGOOD: TP5.1 U5.J7(POWERGOOD)
PMIC_POWERHOLD: J5.1 R23.2 R28.2 U5.G9(GPIO_7/POWERHOLD)
PMIC_RESET_IN: R56.2 U5.K9(RESET_IN) U13.1(~{RESE}T)
PMIC_RESET_OUT: U5.G6(RESET_OUT) U9.1(A)
PMIC_SCE: R19.1 U5.M3(I2C2_SCL_SCE)
PMIC_SDO: R18.1 U5.H8(I2C2_SDA_SDO)
PMIC_VBUS_DET: U5.C13(GPIO_1/VBUSDET) ; also on sheet 14
PMIC_XTAL_IN: C452.1 U5.A3(OSC16MIN) Y9.3
PMIC_XTAL_OUT: C453.1 U5.A2(OSC16MOUT) Y9.1
POR_CT: C109.1 U12.4(CT)
PORz: C95.2 C96.2 R39.1 R57.1 U9.4(Y) U11.AB17(RTC_PORZ) U11.F22(PORZ)
PS_3V3: C23.1 C26.2 C27.2 C33.1 C35.1 C37.1 C39.1 C41.1 C43.1 C45.1 C46.1 C48.1 C111.1 C442.1 P3.1 R7.2 R10.1 R13.1 R29.1 R30.1 R58.1 R407.1 U2.1(VIN.1) U2.2(VIN.2) U5.C4(LDO9_IN) U5.C5(LDOLN_IN) U5.C7(VCC1) U5.D11(SMPS1_IN_1) U5.D12(SMPS1_IN_2) U5.D13(SMPS1_IN_3) U5.E1(SMPS7_IN_B1_1) U5.E2(SMPS7_IN_B1_2) U5.E3(SMPS7_IN_B1_3) U5.F1(SMPS4_IN_1) U5.F2(SMPS4_IN_2) U5.F3(SMPS4_IN_3) U5.G11(SMPS2_IN_1) U5.G12(SMPS2_IN_2) U5.G13(SMPS2_IN_3) U5.H11(SMPS3_IN_1) U5.H12(SMPS3_IN_2) U5.H13(SMPS3_IN_3) U5.J1(SMPS5_IN_1) U5.J2(SMPS5_IN_2) U5.J3(SMPS5_IN_3) U5.L12(LDO34_IN) U5.L13(LDO34_IN_1) U5.M4(NC6) U5.M6(SMPS6_IN) U5.M8(SMPS9_IN) U5.M9(SMPS8_IN) U5.N3(NC7) U5.N4(NC8) U5.N6(SMPS6_IN_1) U5.N8(SMPS9_IN_1) U5.N9(SMPS8_IN_1) U13.5(SENSE1) U13.6(VDD) ; also on sheet 23
PS_3V3_COMP: C11.1 C12.1 U3.6(COMP)
PS_3V3_EN: R9.2 R11.1 U3.3(EN)
PS_3V3_SNS: R13.2 R14.2 U3.5(VSNS)
PS_3V3_SS: C13.1 U3.4(SS)
PS_3V3_TAP: C8.1 C9.1 L2.2 P2.1 R7.1
PWRON: C478.1 R407.2 S1.2(AA) U5.G8(PWRON) ; also on sheet 26
R_3V3LED: D3.2(A) R8.2
R_12VLED: D41.2(A) R240.2
R_EMAC[0]_TXC: R85.2 U14.29(GTX_CLK)
R_EMAC[0]_TXCTL: R84.2 U14.37(TX_EN/TX_CTRL)
R_EMAC[0]_TXD0: R86.2 U14.28(TX_D0)
R_EMAC[0]_TXD1: R87.2 U14.27(TX_D1)
R_EMAC[0]_TXD2: R88.2 U14.26(TX_D2)
R_EMAC[0]_TXD3: R89.2 U14.25(TX_D3)
RESETIN: R52.2 S2.2(AA) U12.3(~{MR}) ; also on sheet 26
RSTOUTn: R38.1 R40.1 R43.1 R318.1 U11.F23(RSTOUTN) U34.2(2B) ; also on sheet 15 17 25 26
RTC_ISO: R57.2 U11.AF14(RTC_ISO)
RTC_X1: C32.1 U6.1(X1) Y1.2
RTC_X2: C31.1 U6.2(X2) Y1.1
RTCK: P4.9(TCKRTN) R63.2
RTCKR: R63.1 U11.E18(RTCK)
SMPS6: C44.1 L8.2 P2.3 R36.1
SMPS_1_2: C34.1 C36.1 L3.2 L4.2 P2.5 R34.1
SMPS_4/5: C40.1 C42.1 L6.2 L7.2 P2.2 R35.1
SW1: L3.1 U5.E11(SMPS1_SW_1) U5.E12(SMPS1_SW_2) U5.E13(SMPS1_SW_3)
SW2: L4.1 U5.F11(SMPS2_SW_1) U5.F12(SMPS2_SW_2) U5.F13(SMPS2_SW_3)
SW3: L5.1 U5.J11(SMPS3_SW_1) U5.J12(SMPS3_SW_2) U5.J13(SMPS3_SW_3)
SW4: L6.1 U5.G1(SMPS4_SW_1) U5.G2(SMPS4_SW_2) U5.G3(SMPS4_SW_3)
SW5: L7.1 U5.H1(SMPS5_SW_1) U5.H2(SMPS5_SW_2) U5.H3(SMPS5_SW_3)
SW6: L8.1 U5.M5(SMPS6_SW_1) U5.N5(SMPS6_SW)
SW7: L26.1 U5.D1(SMPS7_SW_1) U5.D2(SMPS7_SW_2) U5.D3(SMPS7_SW_3)
SW8: L9.1 U5.M10(SMPS8_SW) U5.N10(SMPS8_SW_1)
SW9: L25.1 U5.M7(SMPS9_SW) U5.N7(SMPS9_SW_1)
TCK: R64.1 U11.E20(TCLK)
TCLK: P4.11(TCLK) R64.2
TDI: P4.3(TDI) U11.D23(TDI)
TDO: P4.7(TDO) R61.2
TDOR: R61.1 U11.F19(TDO)
TESTV: TP9.1 U5.N12(VPROG/TESTV)
TMP102_ALERT: R15.2 U4.3(ALERT) ; also on sheet 27
TMS: P4.1(TMS) U11.F18(TMS)
TPS_ENABLE1: TP7.1 U5.J5(ENABLE1)
TPS_PWRDOWN: TP8.1 U5.K8(PWRDOWN)
TPS_RST: R53.1 R55.2 U12.1(~{RESE}T)
TRSTN: P4.2(TRSTn) R66.1 U11.D20(TRSTN)
U1-1: C1.2 U1.1(BOOT)
U1-3: R3.2 R6.1 U1.3(EN)
U1-4: C4.1 U1.4(SS)
U1-8: C1.1 D1.1(CATHODE) L1.1 U1.8(PH)
U2-6: C10.1 U2.6(CT)
U3-1: C7.2 U3.1(BOOT)
U3-8: C7.1 D2.1(CATHODE) L2.1 U3.8(PH)
U5_C8: C25.2 U5.C8(LDOVANA_OUT)
U13-4: C112.1 U13.4(CT)
U32_ADJ: C443.1 R396.2 R397.1 U32.4(ADJ)
USB2_VBUS: R411.1 U5.D8(VBUS) ; also on sheet 14
VBG: C16.2 U5.B7(VBG)
VUSB_3V3: C18.2 U5.B9(LDOUSB_OUT) ; also on sheet 14
WAKEUP1: R50.1 U11.AC17(WAKEUP1)
WAKEUP2: R51.1 U11.AB16(WAKEUP2)
N23410845: C98.2 U10.4(Y) U11.E23(RESETN)
N23730763: C197.1 C198.1 C199.1 C200.1 C203.1 L10.3 U11.M14(VDDA_ABE_PER) U11.N11(VDDA_DEBUG) U11.N12(VDDA_DSP) U11.N16(VDDA_MPU) U11.P14(VDDA_VIDEO) U11.P15(VDDA_GMAC_CORE) U11.P16(VDDA_DDR) U11.R14(VDDA_GPU) U11.R17(VDDA_IVA)
N24165486: C201.1 C202.1 C204.1 L11.1 U11.V13(VDDA_SATA) U11.W12(VDDA_USB3)
N26024435: C497.1 C498.1 C499.1 L24.1 U11.AA16(VDDA_PCIE1) U11.AA17(VDDA_PCIE0) U11.W14(VDDA_PCIE) U11.Y17(VDDA_HDMI)
N28613451: R318.2 R319.2 U5.E6(NRESWARM)
N28614009: R322.2 R323.2 R433.1 U5.E5(NSLEEP)
N29245750: R422.1 U11.AE14(RTC_OSC_XI_CLKIN32)
N29286052: R405.2 U9.3(B) U34.1(2A) U34.3(2Y)
N29286254: C476.1 U34.7(2Y)
N29286257: C476.2 R404.1 U34.5(2A) U34.6(2B)
N29975844: C496.1 U5.C1(OSC16MCAP)
N30391816: Q9.1(BASE) R423.2 R430.1 U43.2(CATHODE)
N30391875: R424.2 R425.1 R430.2 U43.1(REF)
N30606654: Q8.1(BASE) R418.2 R429.1 U35.2(CATHODE)
N30606697: R419.2 R420.1 R429.2 U35.1(REF)
N31260694: P5.28(LED1_C) R68.1
N31260700: P5.30(LED2_C) R69.2
N31260959: P5.34(LED4_C) R98.2
N31261983: P5.32(LED3_C) R97.1
N31304297: R477.2 U14.18(CLK_OUT)
N31316106: R479.2 U14.14(XO)

Not connected (* = marked no-connect by the designer): P4 6(KEY)* 17(EMU2)* 18(EMU3)* 19(EMU4)*; P5 M1 M2; U5 B4(GPADC_REF) C9(NC4)* C11(RPWRON) K4(NC2)* K5(NC5)* K10(GPIO_4/SYSEN1)* L4(NC3)* M11(CLK32KGO)* N11(GPIO_6/SYSEN2)*; U11 AD14(RTC_OSC_XO)*; U13 3(~{MR}); U14 13(VDDA1P8_1) 20(JTAG_CLK)* 21(JTAG_TDO)* 22(JTAG_TMS)* 23(JTAG_TDI)* 39(GPIO_0) 40(GPIO_1) 46(LED_1) 48(VDDA1P8_2)

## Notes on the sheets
sheet 1
- REV
- DESCRIPTION
- DATE
- BY
- A4
- * Changed PHY to DP83867IRRGZ
  * Changed RJ45 to 0845-2D1T-E4
  * Changed micro SD Connector
- 07/17/2018
- TI
- P01 TITLE PAGE
- P02 12V INPUT, 3.3V AND 5V SWITCHERS
- P03 TPS6590376 1 CONTROL
- P04 TPS6590376 2 RESET, & RTC
- P05 TPS6590376 3  MPU,DDR, & DSP SWITCHERS
- P06 TPS6590376 4 CORE & 1.8V
- P07 AM572X CORE POWER & EEPROM
- P08 AM572X CLOCKS AND RESET
- P09 AM572X IO POWER AND GROUND
- P10 AM572X DDR3 POWER & JTAG
- P11 AM572X ETHERNET 1
- P12 AM572X ETHERNET 2
- P13 AM572X GPMC & LCD
- P14 AM572X USB INTERFACES
- P15 AM572X I/O, LEDs, AND GPIO
- P16 AM572X AUDIO & DEBUG SERIAL
- P17 AM572X HDMI PORT
- P18 AM572X eMMC, MMC3, & uSD
- P19 AM572X DDR INTERFACE 1
- P20 AM572X DDR INTERFACE 2
- P21 DDR3 BANK 1
- P22 DDR3 BANK 2
- P23 DDR3 BANK 2 CAPS & TERM
- P24 DDR3 BANK 1 CAPS & TERM
- P25 USB & SATA CONNECTOR
- P26 PCIe, SATA, & SERDES CLOCK
- P27 EXPANSION HEADERS
- P28 MECHANICAL
sheet 2
- 12VDC TO 5VDC 4A
- VBATT
  12V
- 4A
- AUXILLIARY 5VDC
  FAN CONNECTOR.
- 5V
- GND
- 12VDC MAIN POWER INPUT
- Undervoltage lockout..11.6V
- 500mA
- DC
- 12VDC TO 3.3VDC 4A
- POWER LED
- Undervoltage lockout..11.6V
- TEMPERATURE SENSOR
- CURRENT MEASUREMENT CONNECTOR
sheet 3
- PMIC
- POWER BUTTON
- * BOOT0=0: SMPS3 = 1.35V (DDR3L)
    BOOT0=1: SMPS3 = 1.50V (DDR3)
  * BOOT1=0: Single PORz release at startup,
                       no PORz during warm reset
    BOOT1=1: Double PORz release at startup,
                       PORz assertion during warm reset
- TPS6590376ZWSR
- Insert wire here to enable use
  of the JTAG without  boot
  image present.
sheet 4
- 3.3V (3.3V I/O)
- 1.8V
- 3.3V
- 3.3V
- 1.8V
- 1.0V
- 1.8V
- TPS6590376ZWSR
- Real Time Clock
sheet 5
- AVS
- 1.35V
- AVS
- 4A
sheet 6
- AVS
- 1A
- 2.5V
- 500 mA
- 1.8V
- 1.0V
- 500 mA
sheet 7
- NO CONNECT ON
  J6ECO
- BOARD ID EEPROM
- WRITE ENABLE
sheet 8
- WARM RESET TO
  POWER ON RESET
  TRIGGER.
- RESET BUTTON
- 0.9V TRIP
- SET FOR PORZ ONLY
sheet 10
- JTAG HEADER.
